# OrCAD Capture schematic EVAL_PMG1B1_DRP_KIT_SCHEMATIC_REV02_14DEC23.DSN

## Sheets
1 11: REVISION HISTORY: title: EVAL_PMG1_B1_DRP Kit; rev: 02; note: 630-60657-01
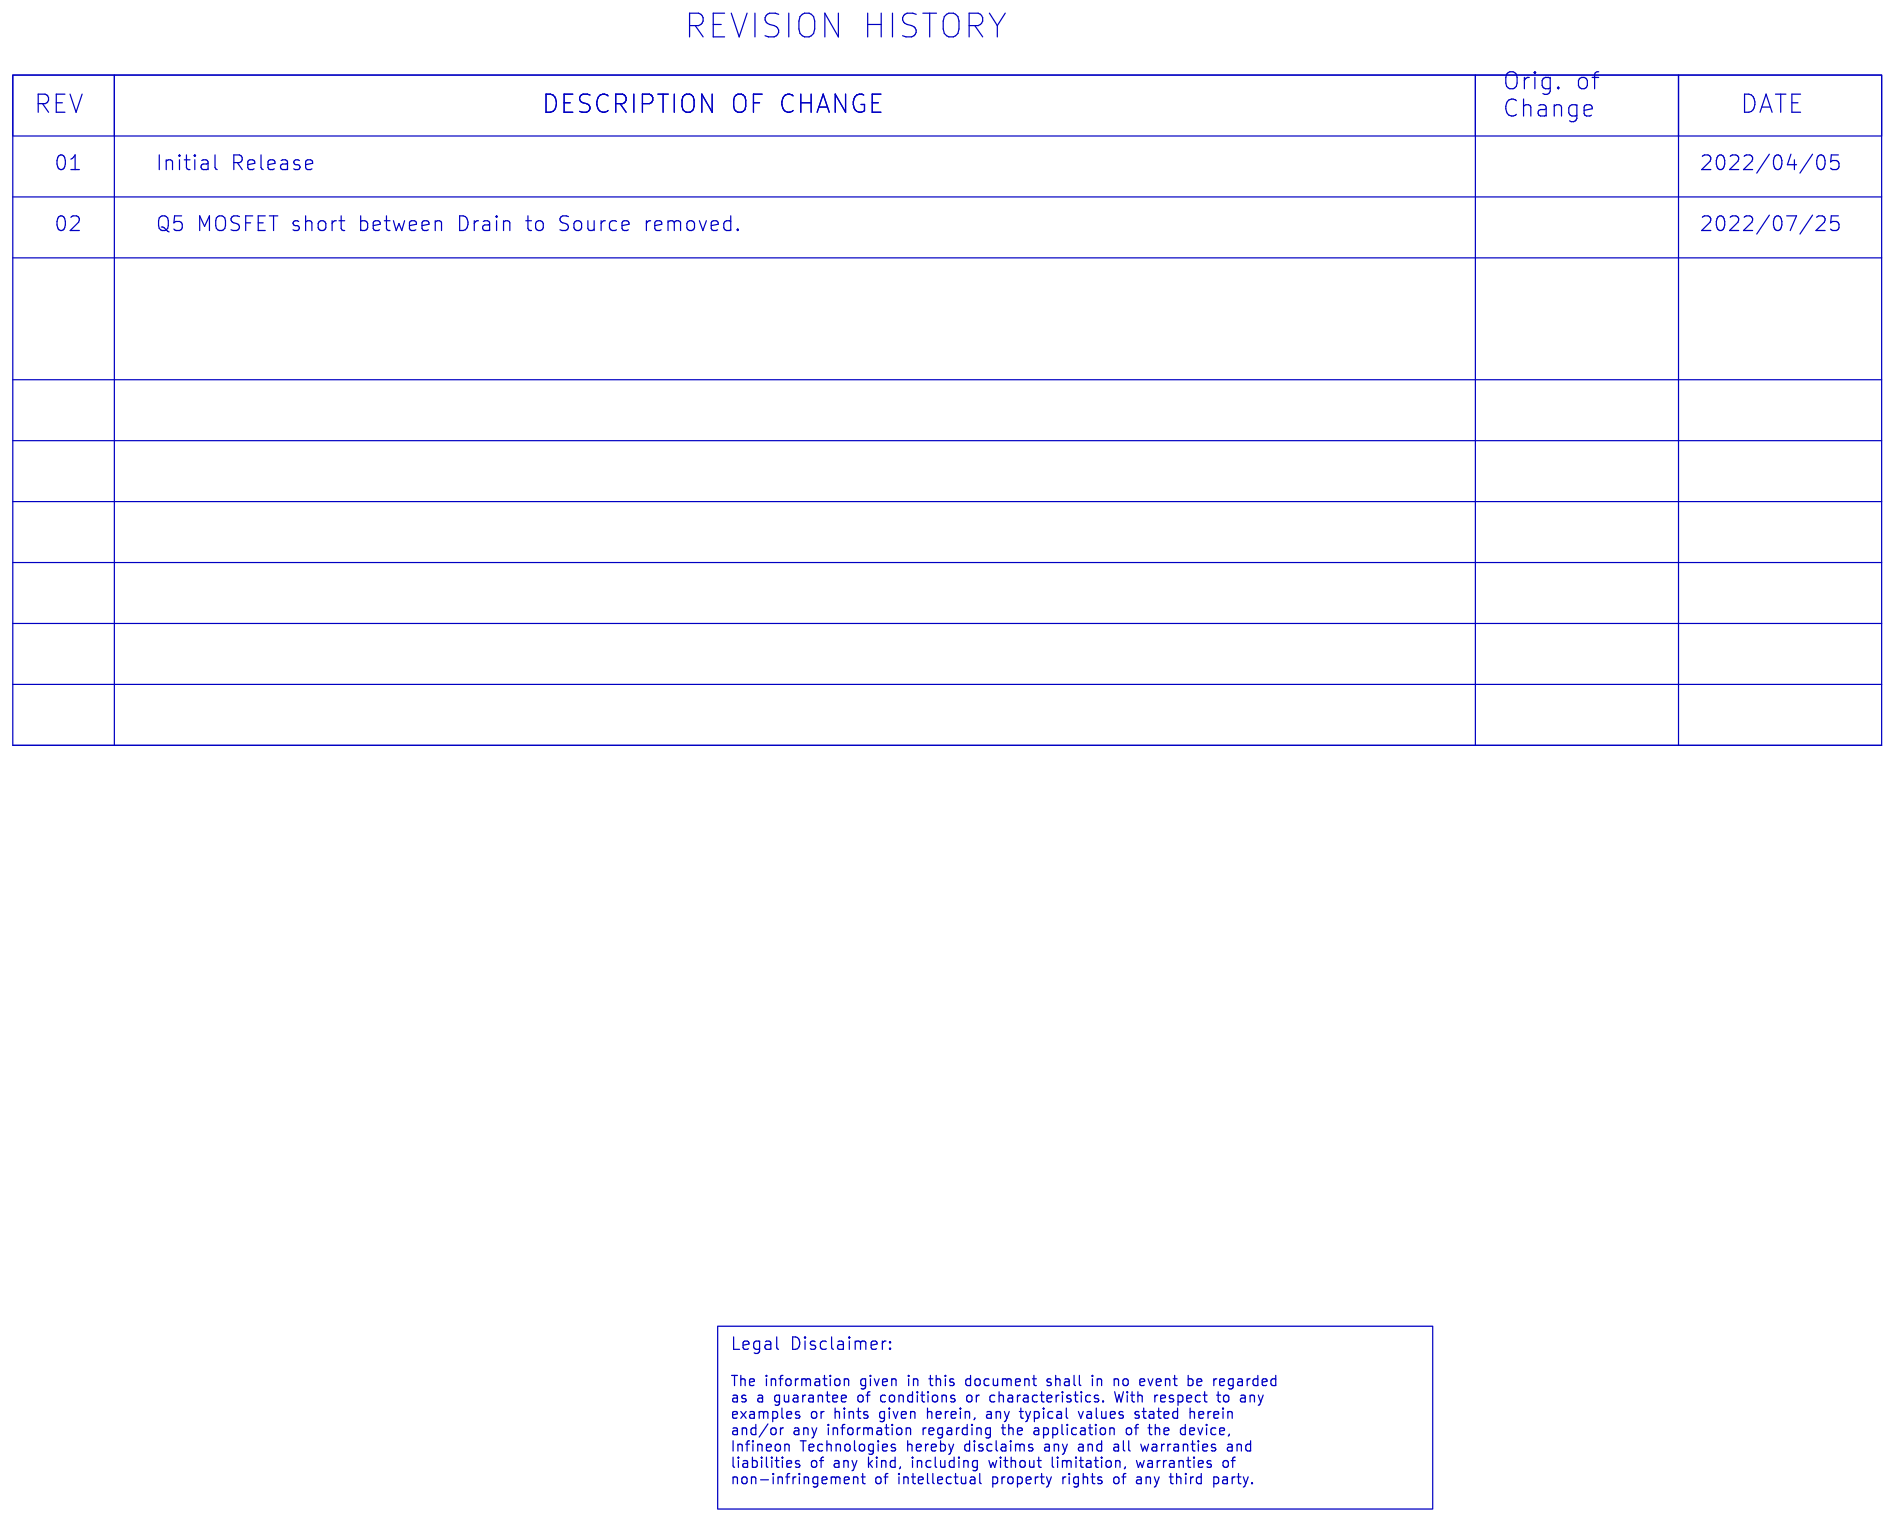
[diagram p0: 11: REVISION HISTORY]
2 10: ACCESSORIES
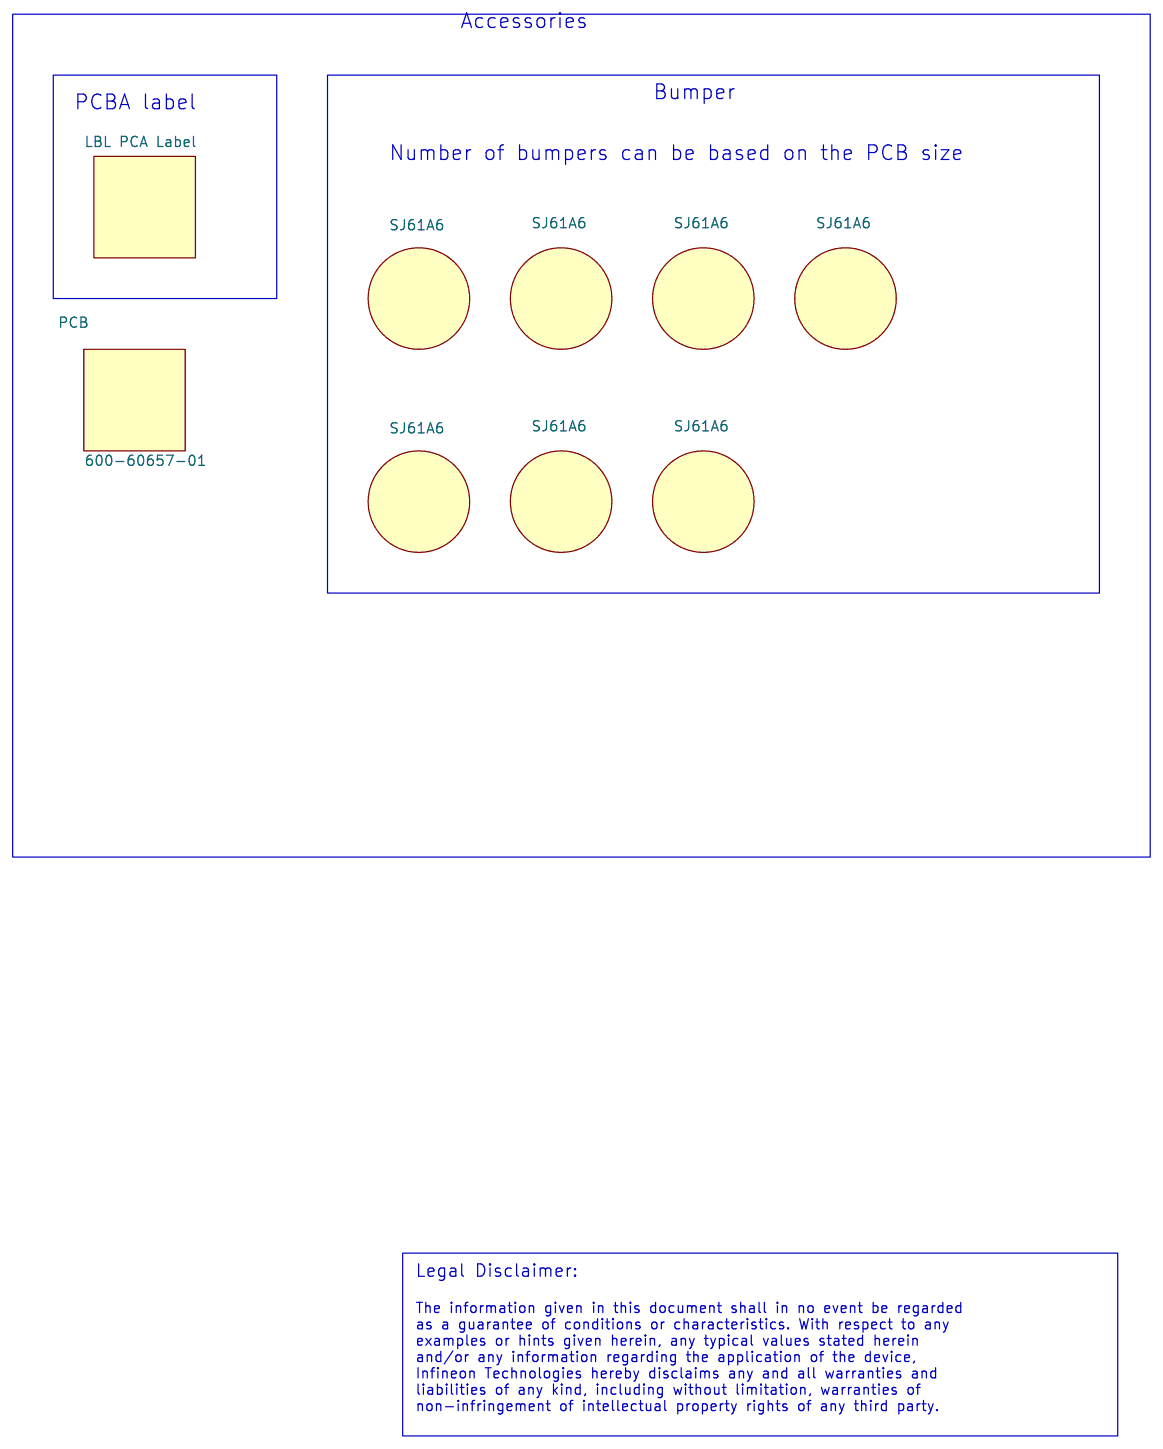
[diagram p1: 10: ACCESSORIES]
3 03: KITPROG3: size A4
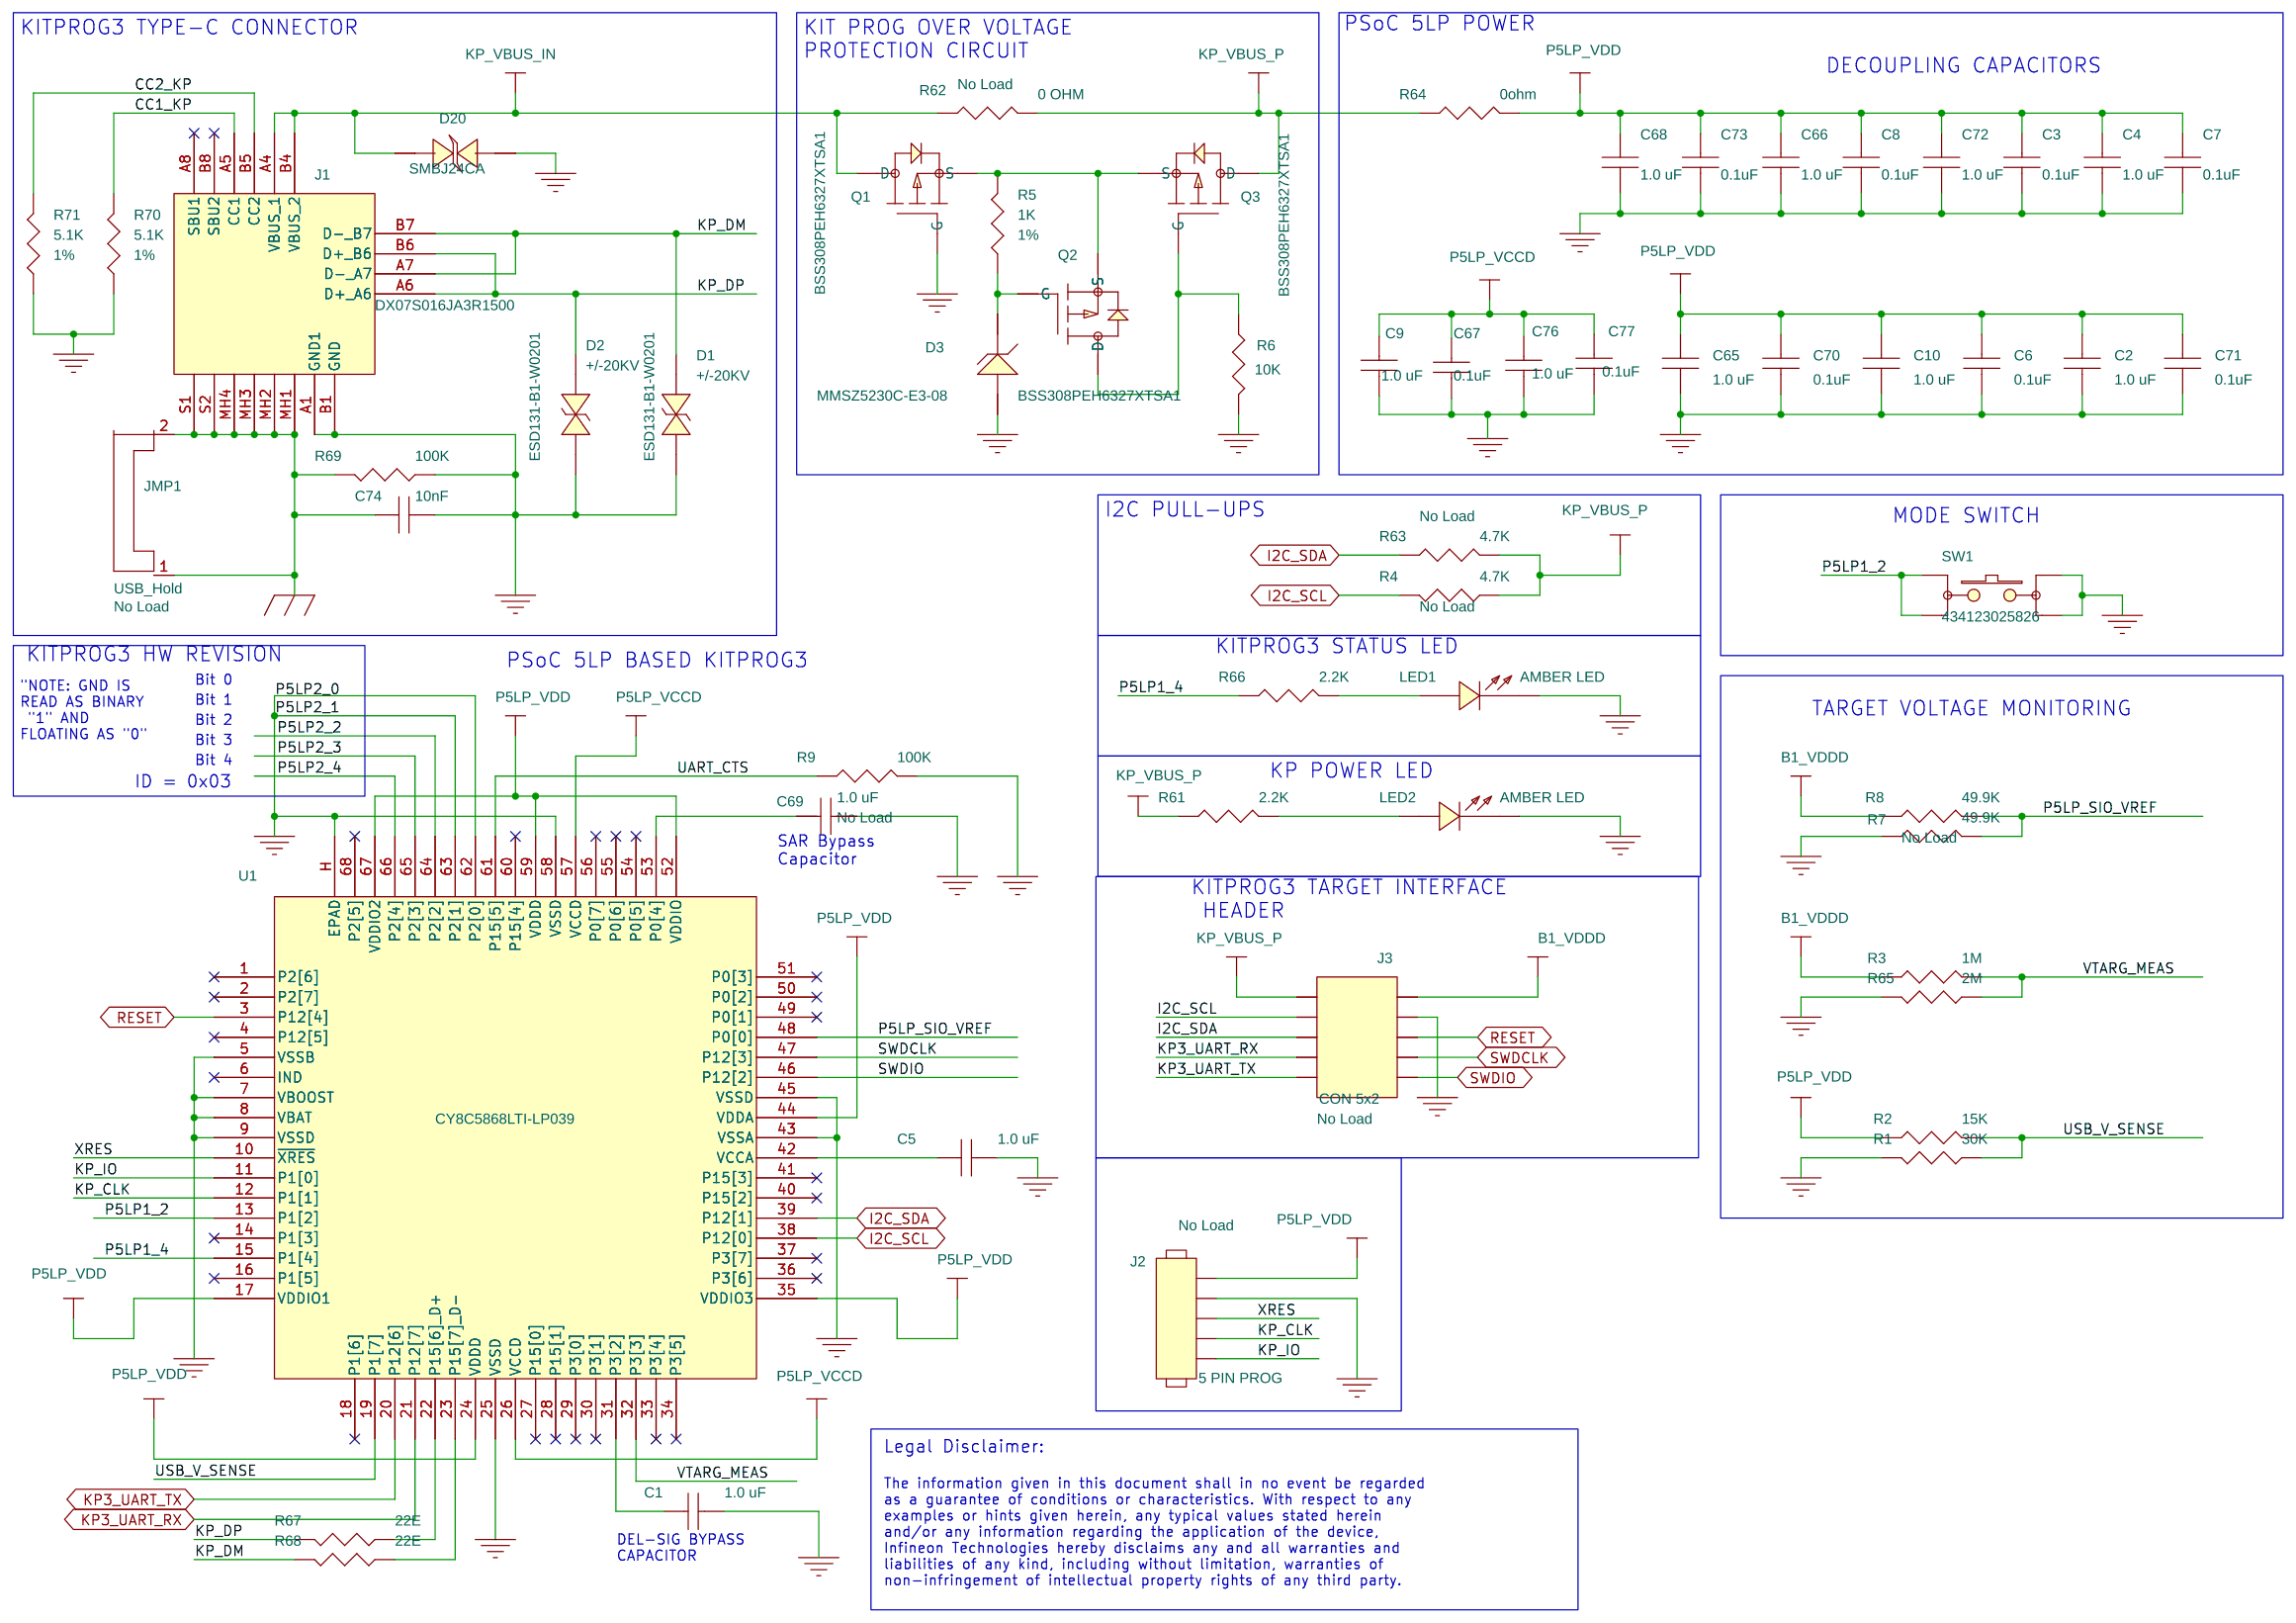
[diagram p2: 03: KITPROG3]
4 02: BLOCK DIAGRAM
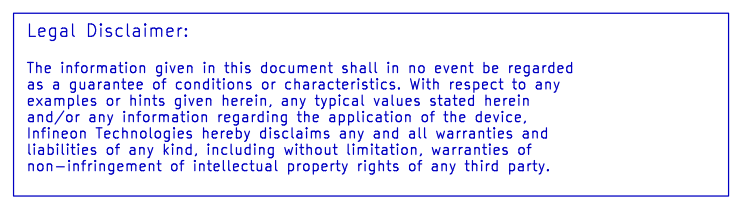
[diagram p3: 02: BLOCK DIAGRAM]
5 05: PMG1-B1 CONTROLLER: size A4
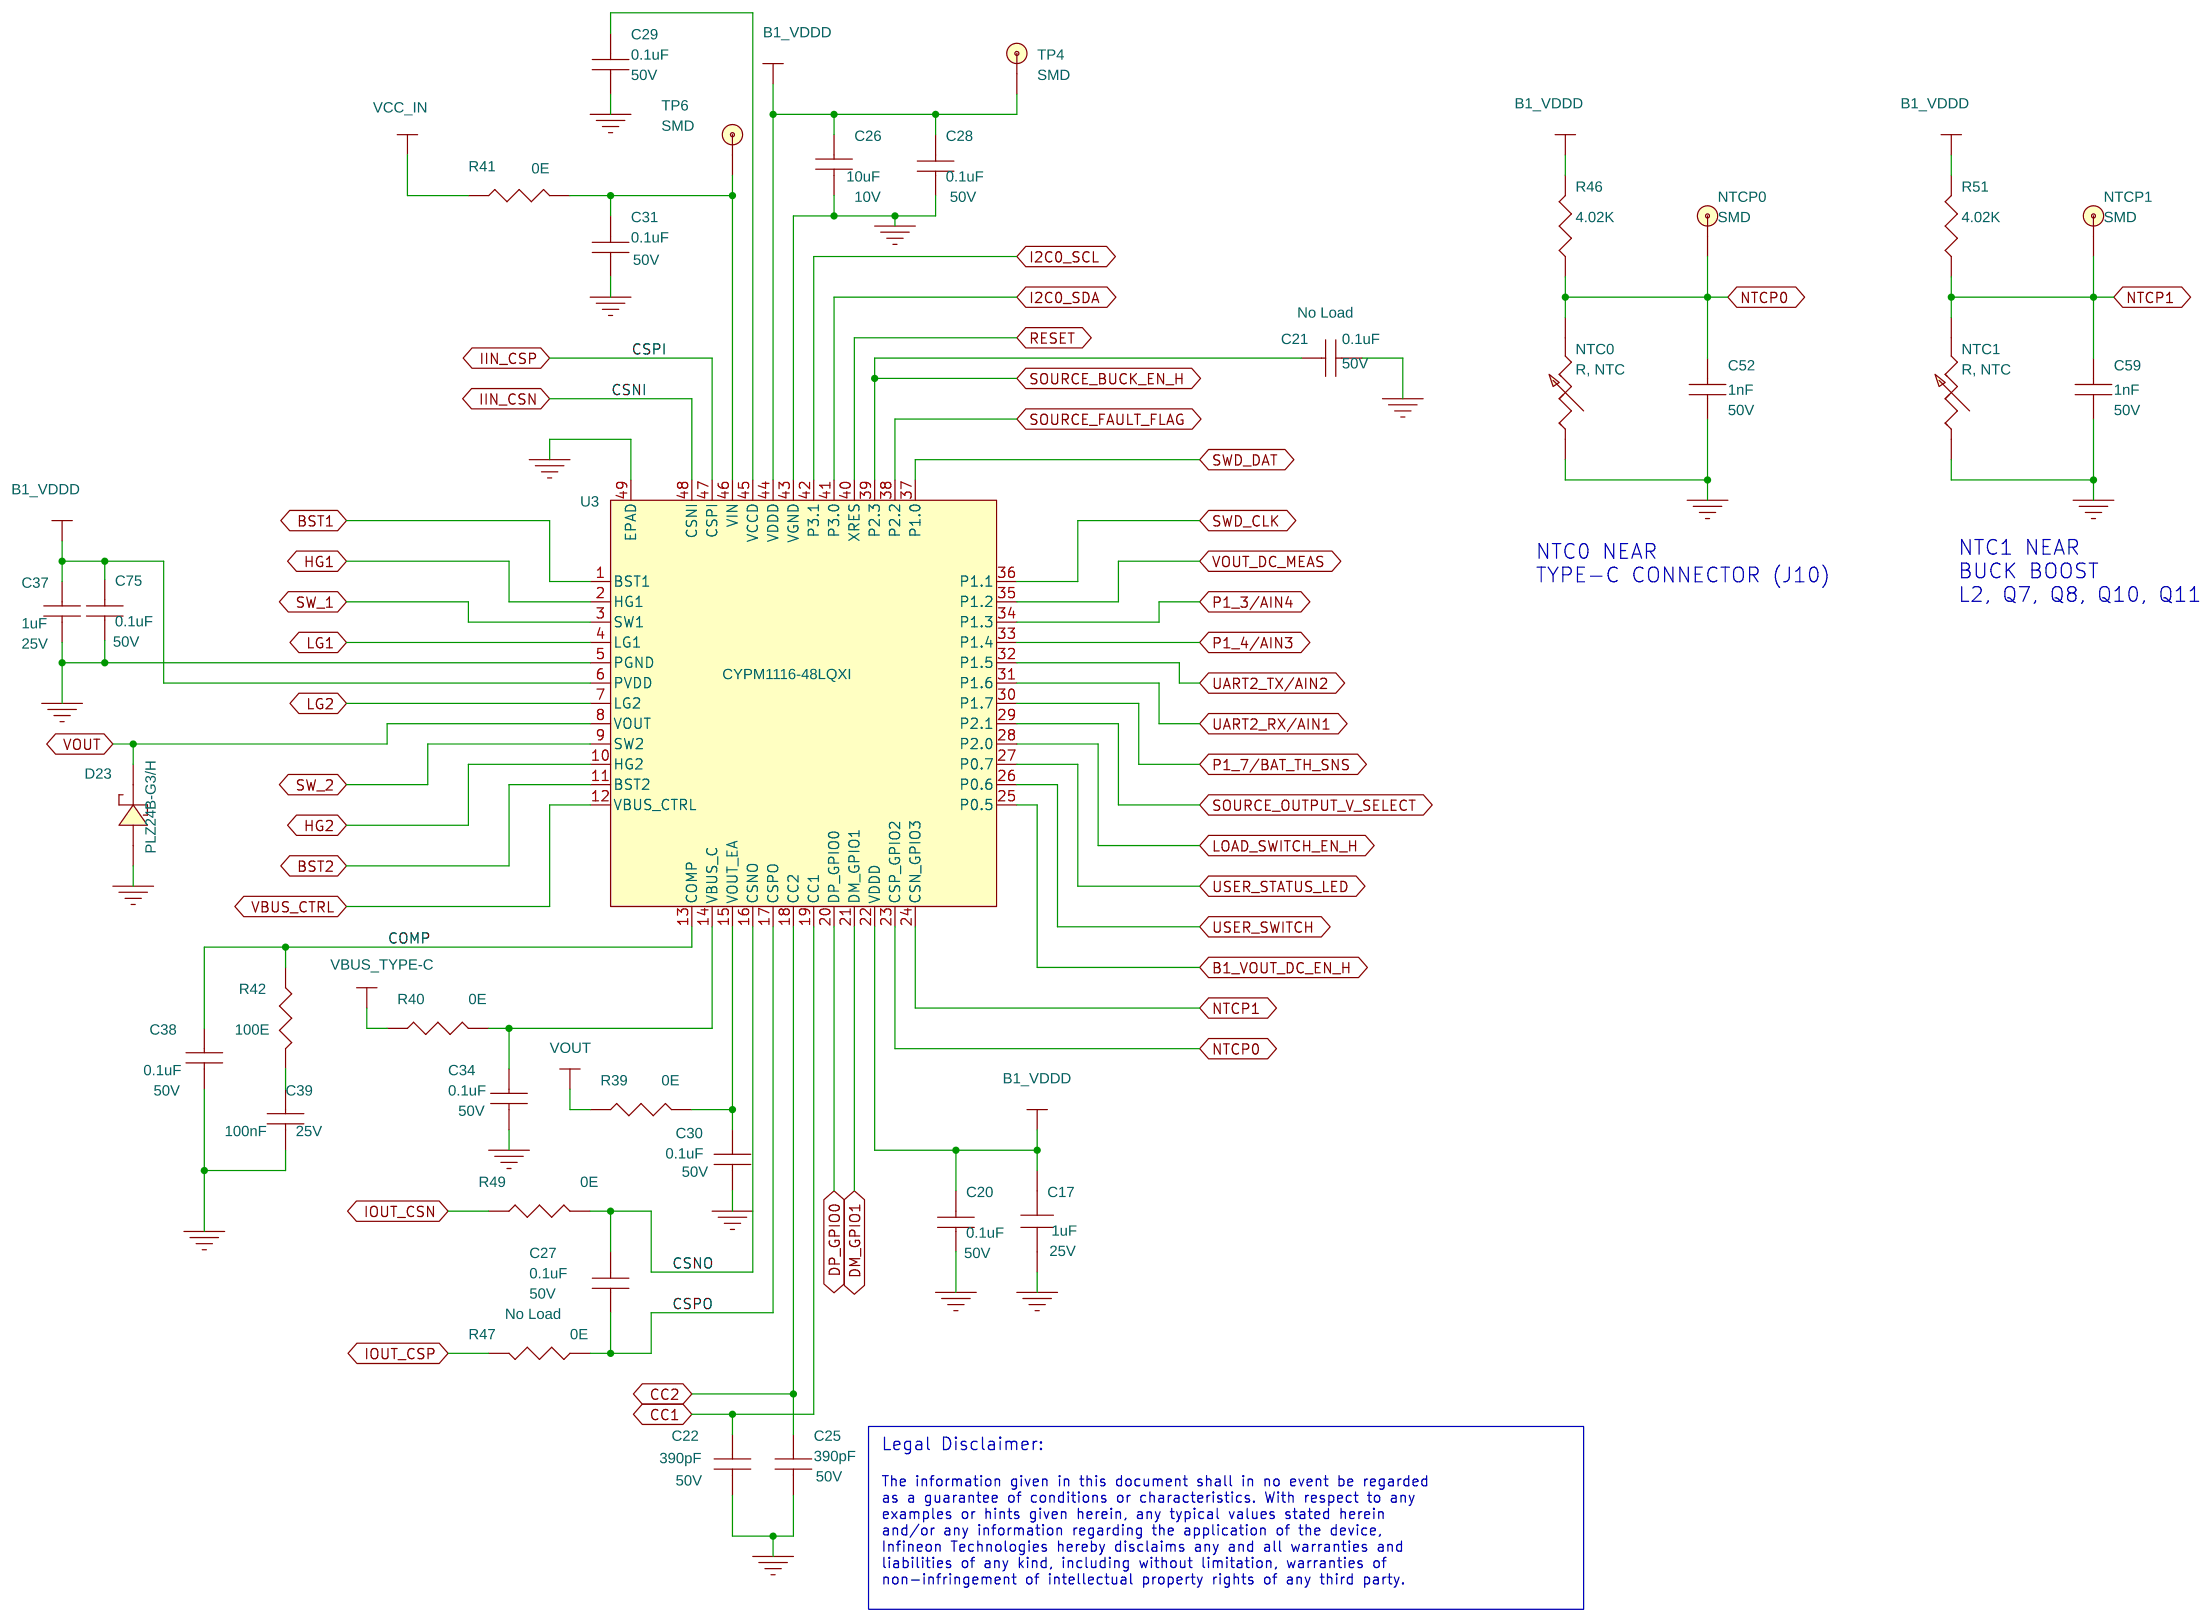
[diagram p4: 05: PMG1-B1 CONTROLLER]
6 06: INTERFACE SIGNALS: size A4
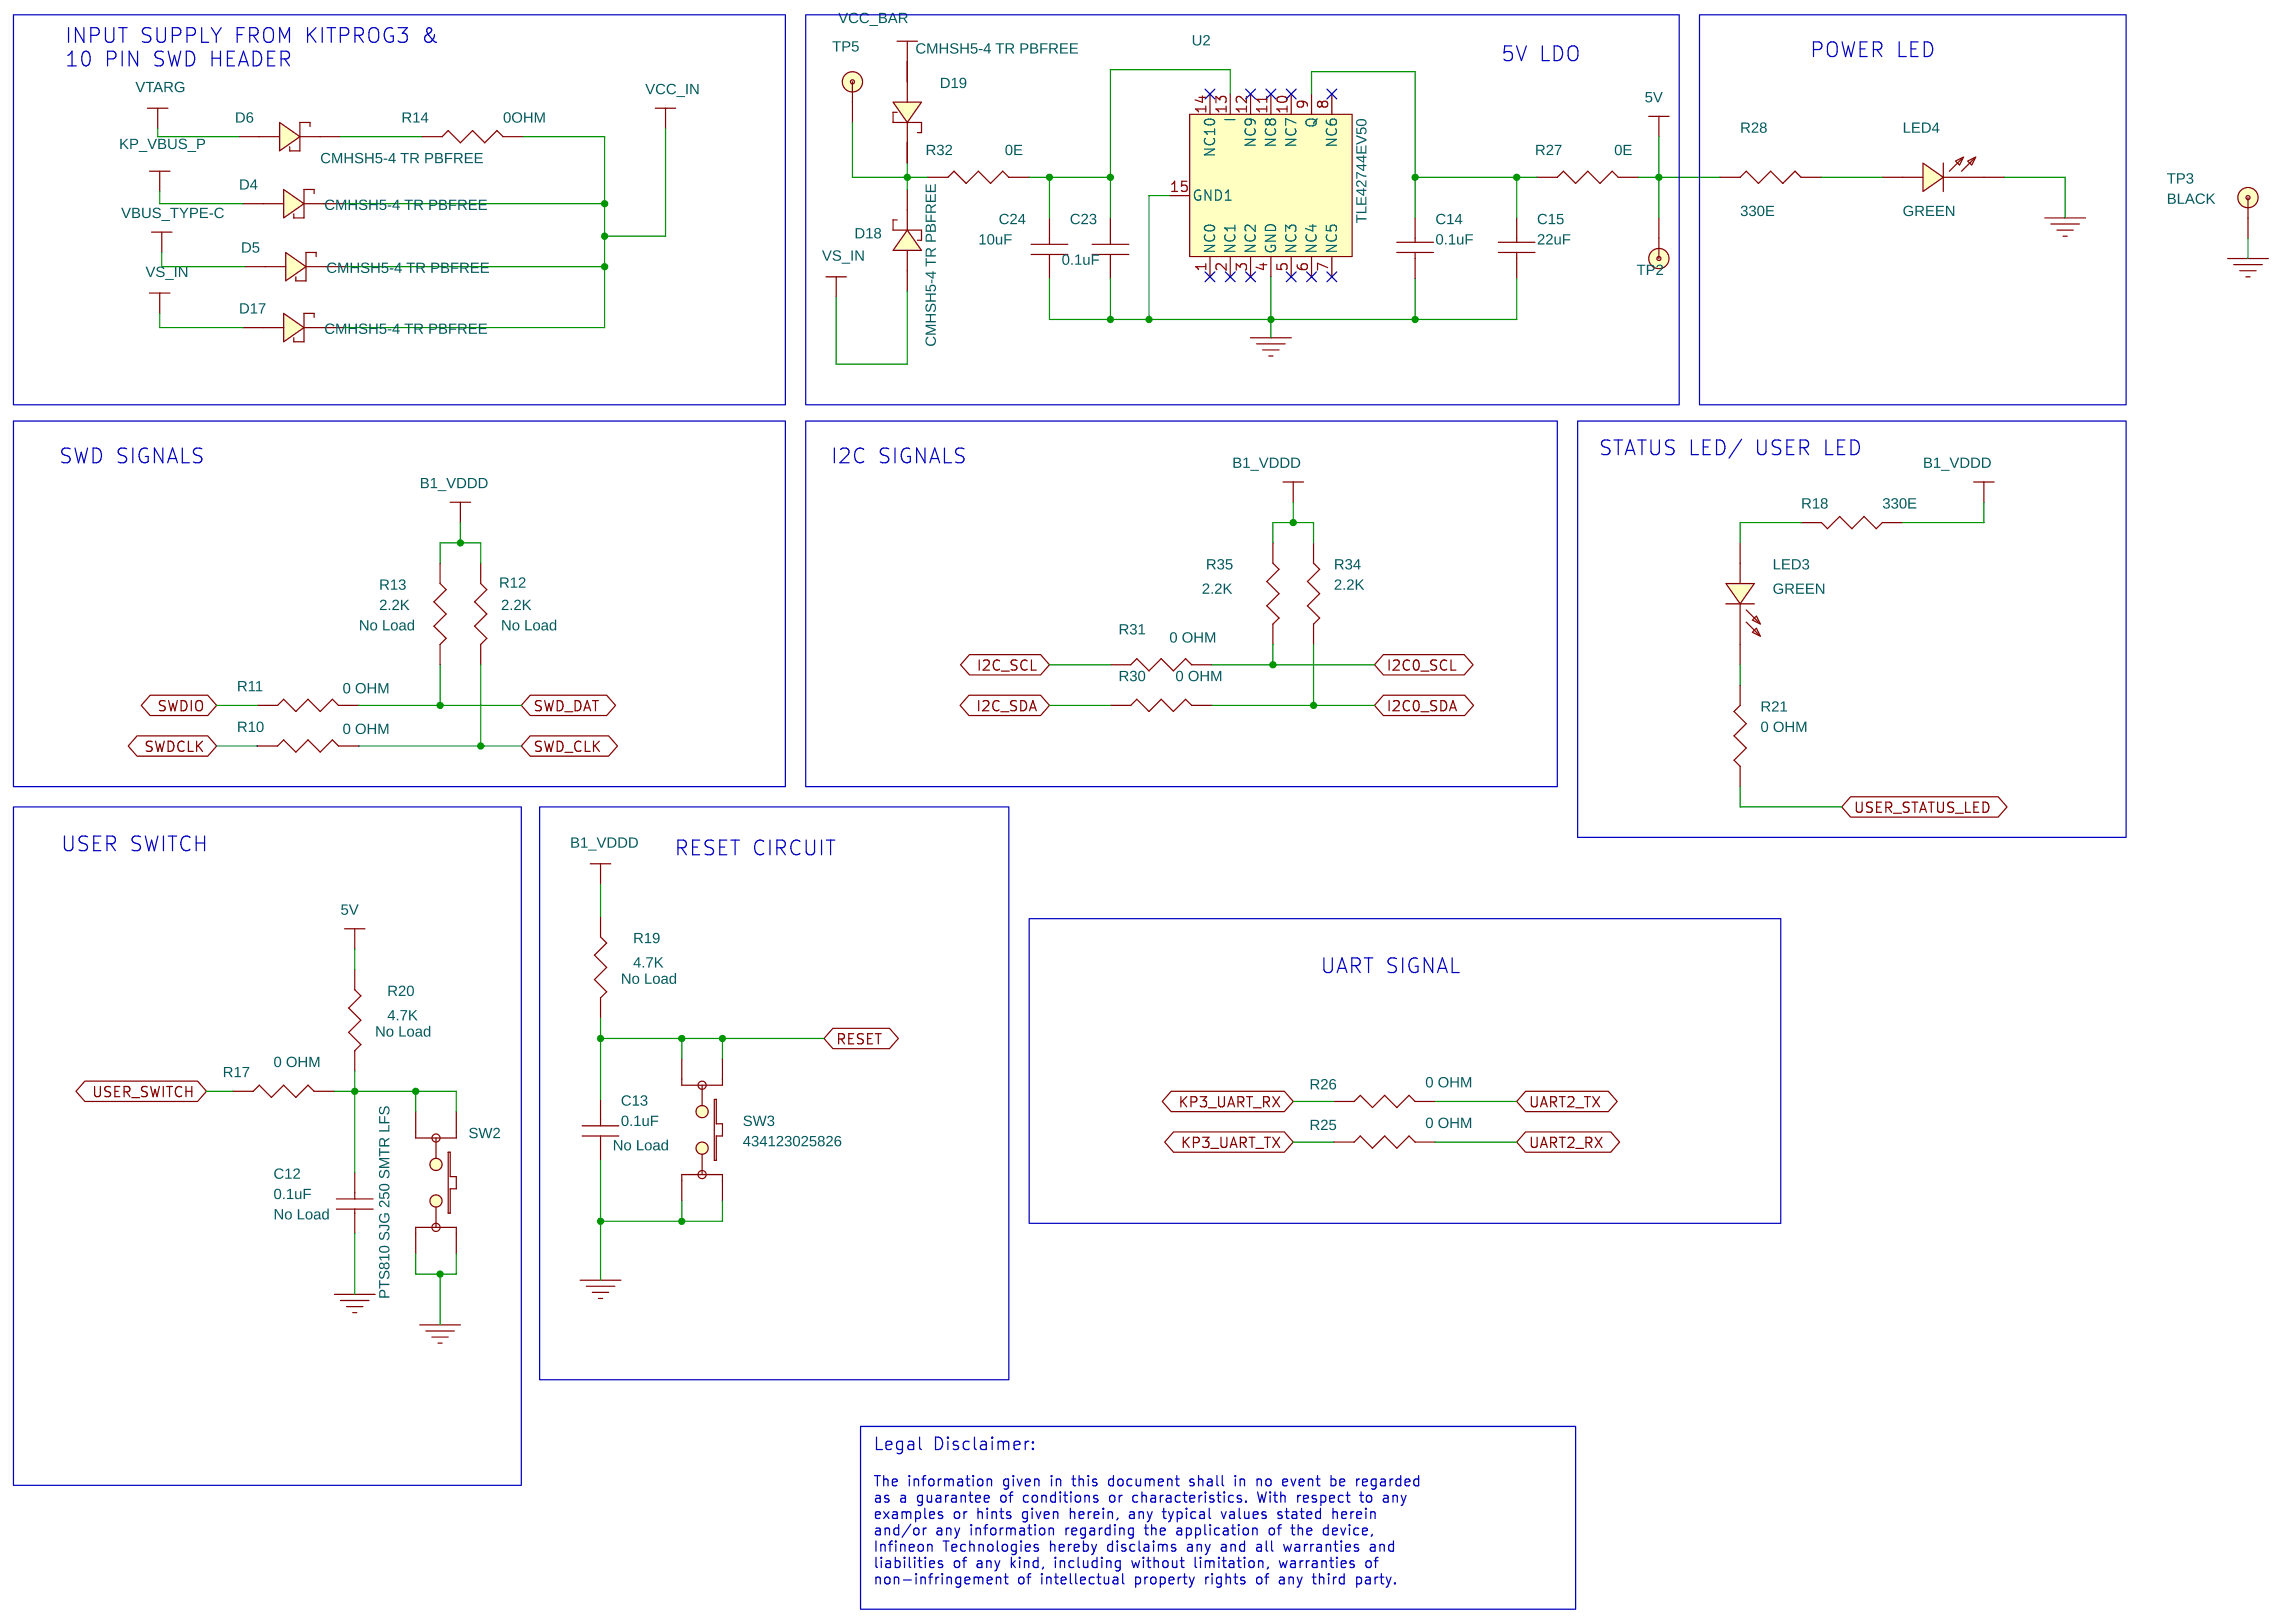
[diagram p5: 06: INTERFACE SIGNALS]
7 08: SOURCE BUCK (27W MAX): size A4
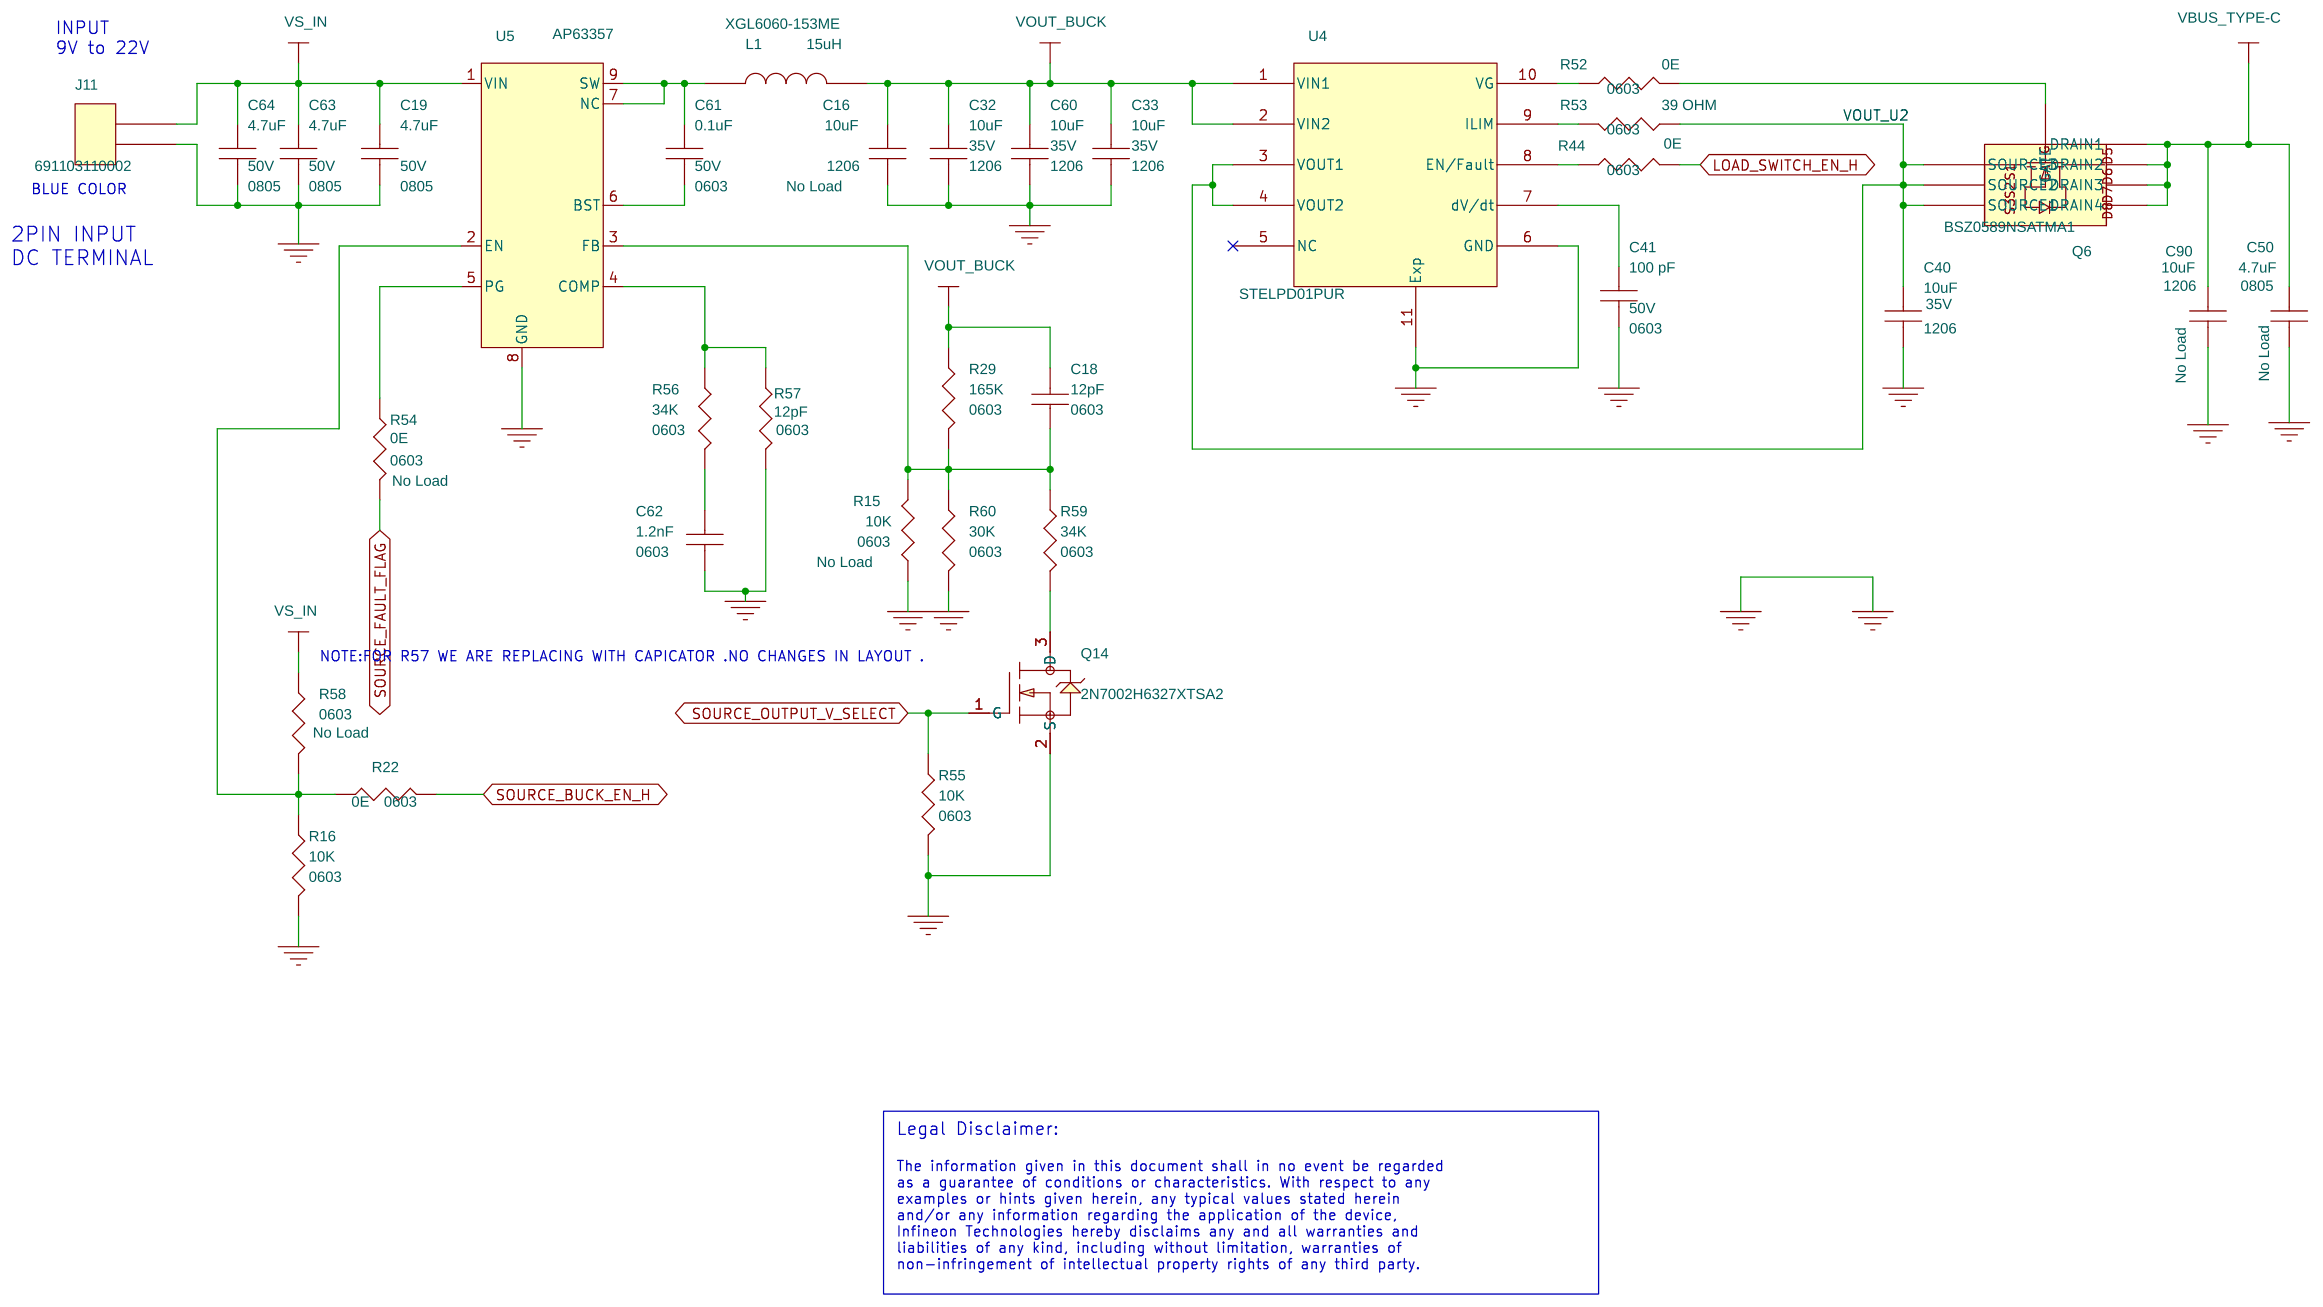
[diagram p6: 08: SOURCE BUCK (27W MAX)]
8 07: CONNECTOR INTERFACES: size A4
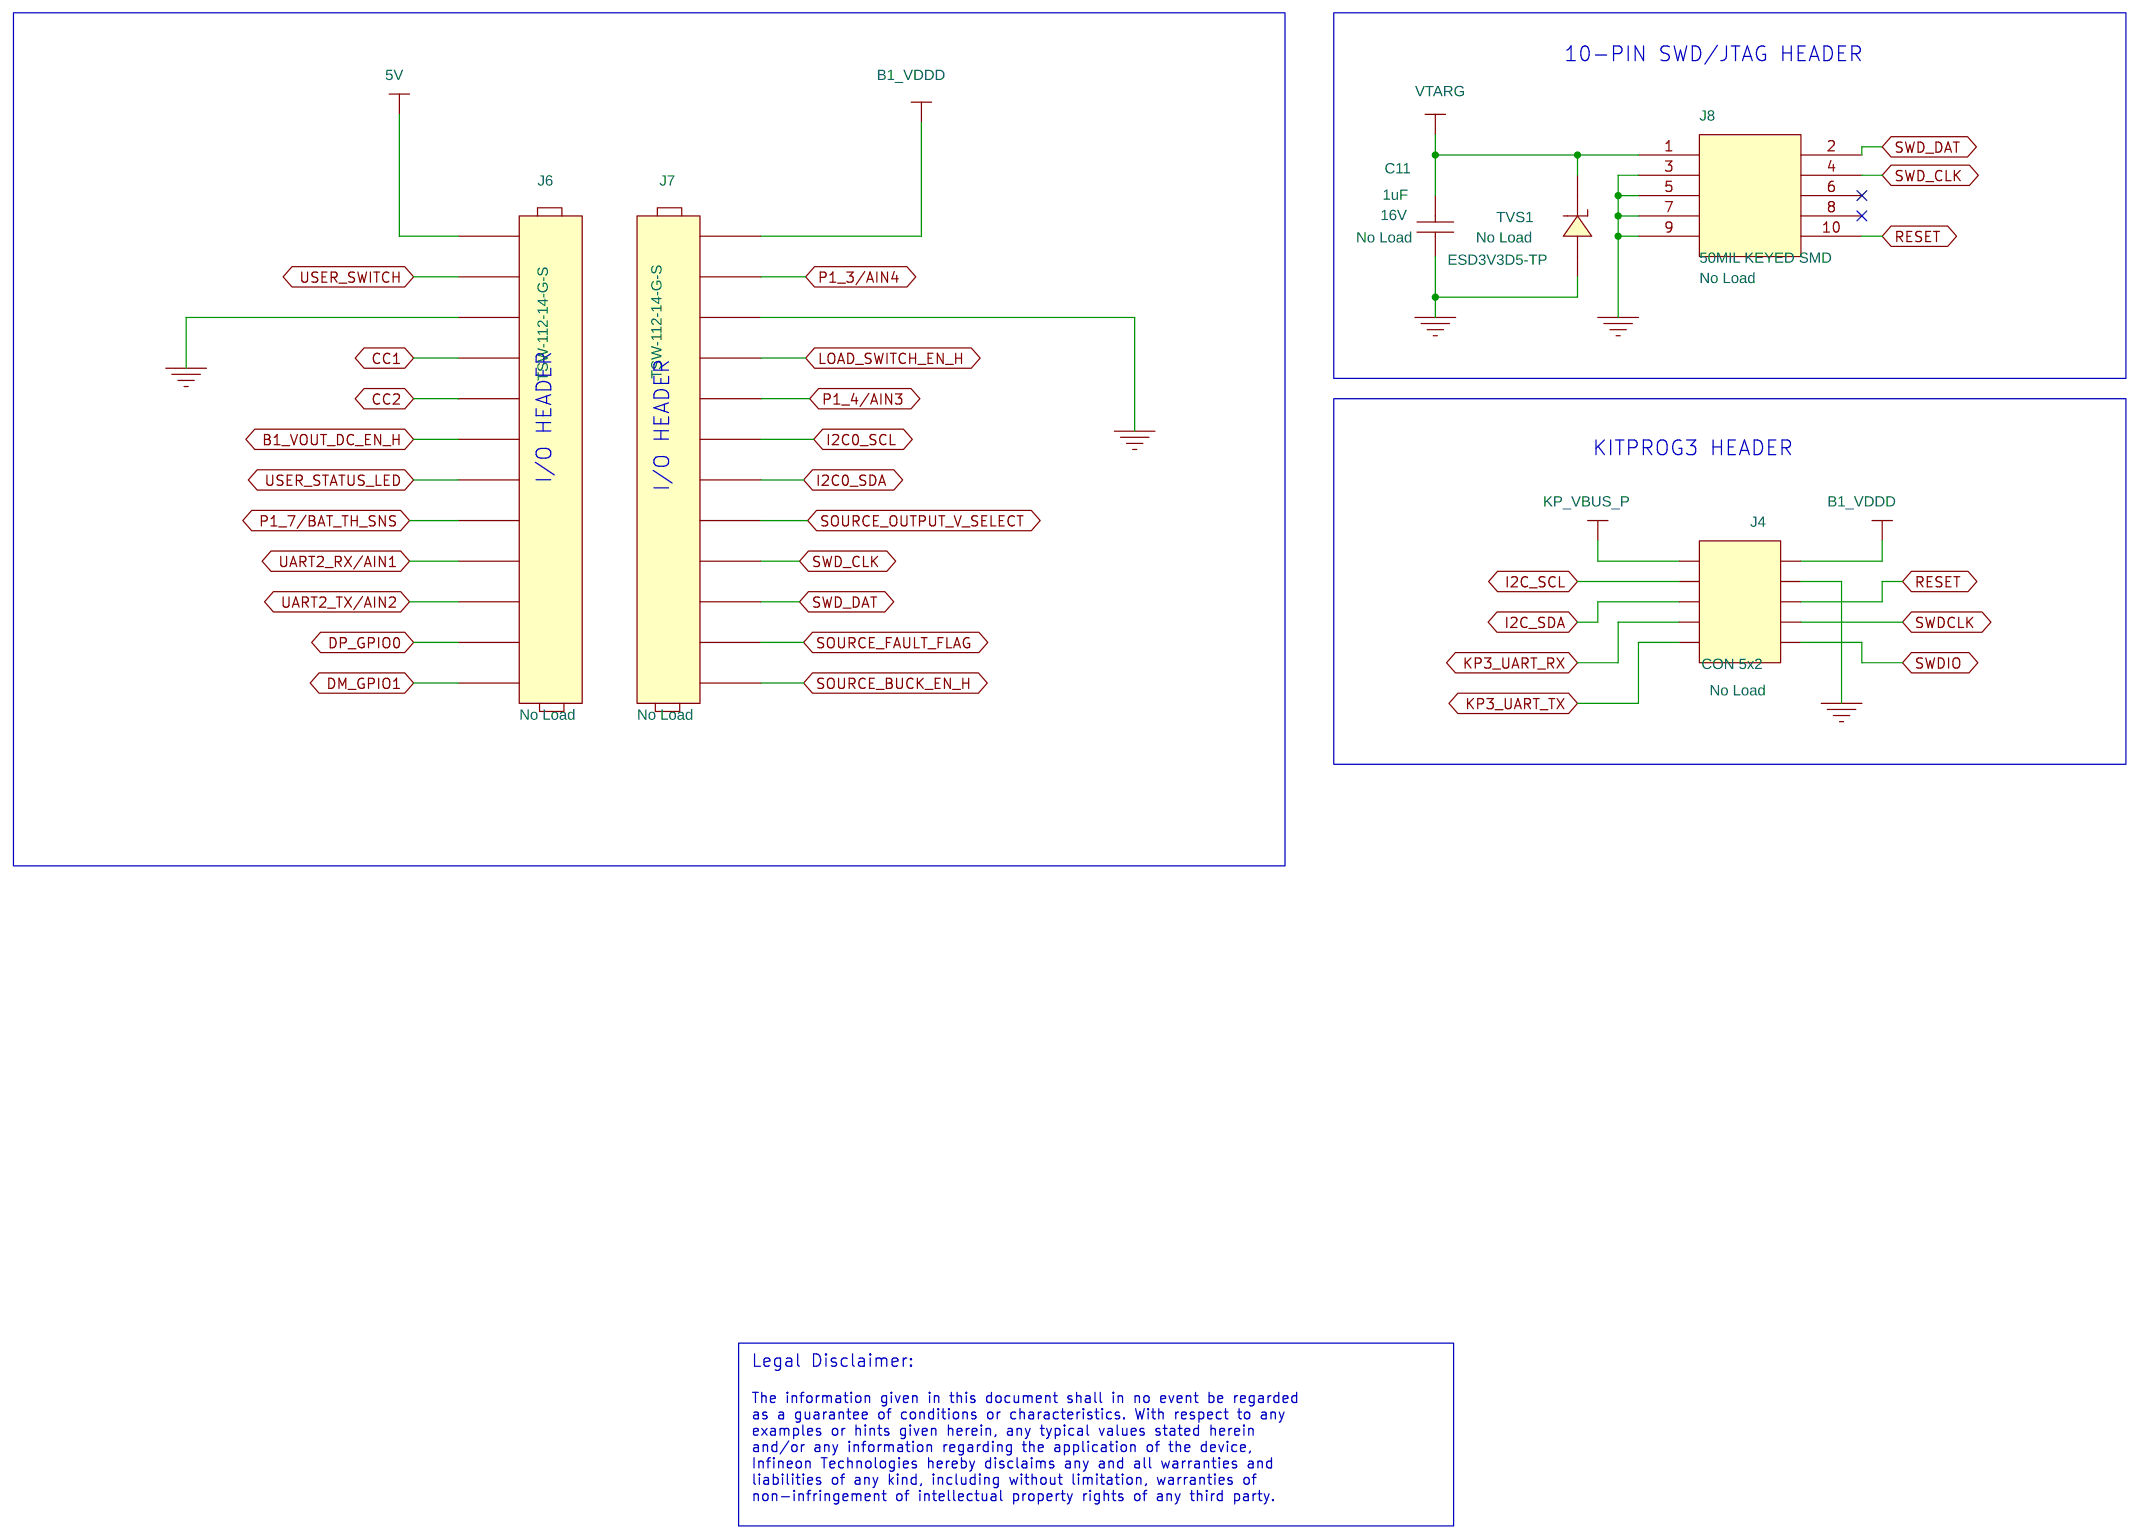
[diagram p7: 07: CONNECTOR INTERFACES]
9 09: BATTERY CELL & TEMPERATURE: size A4
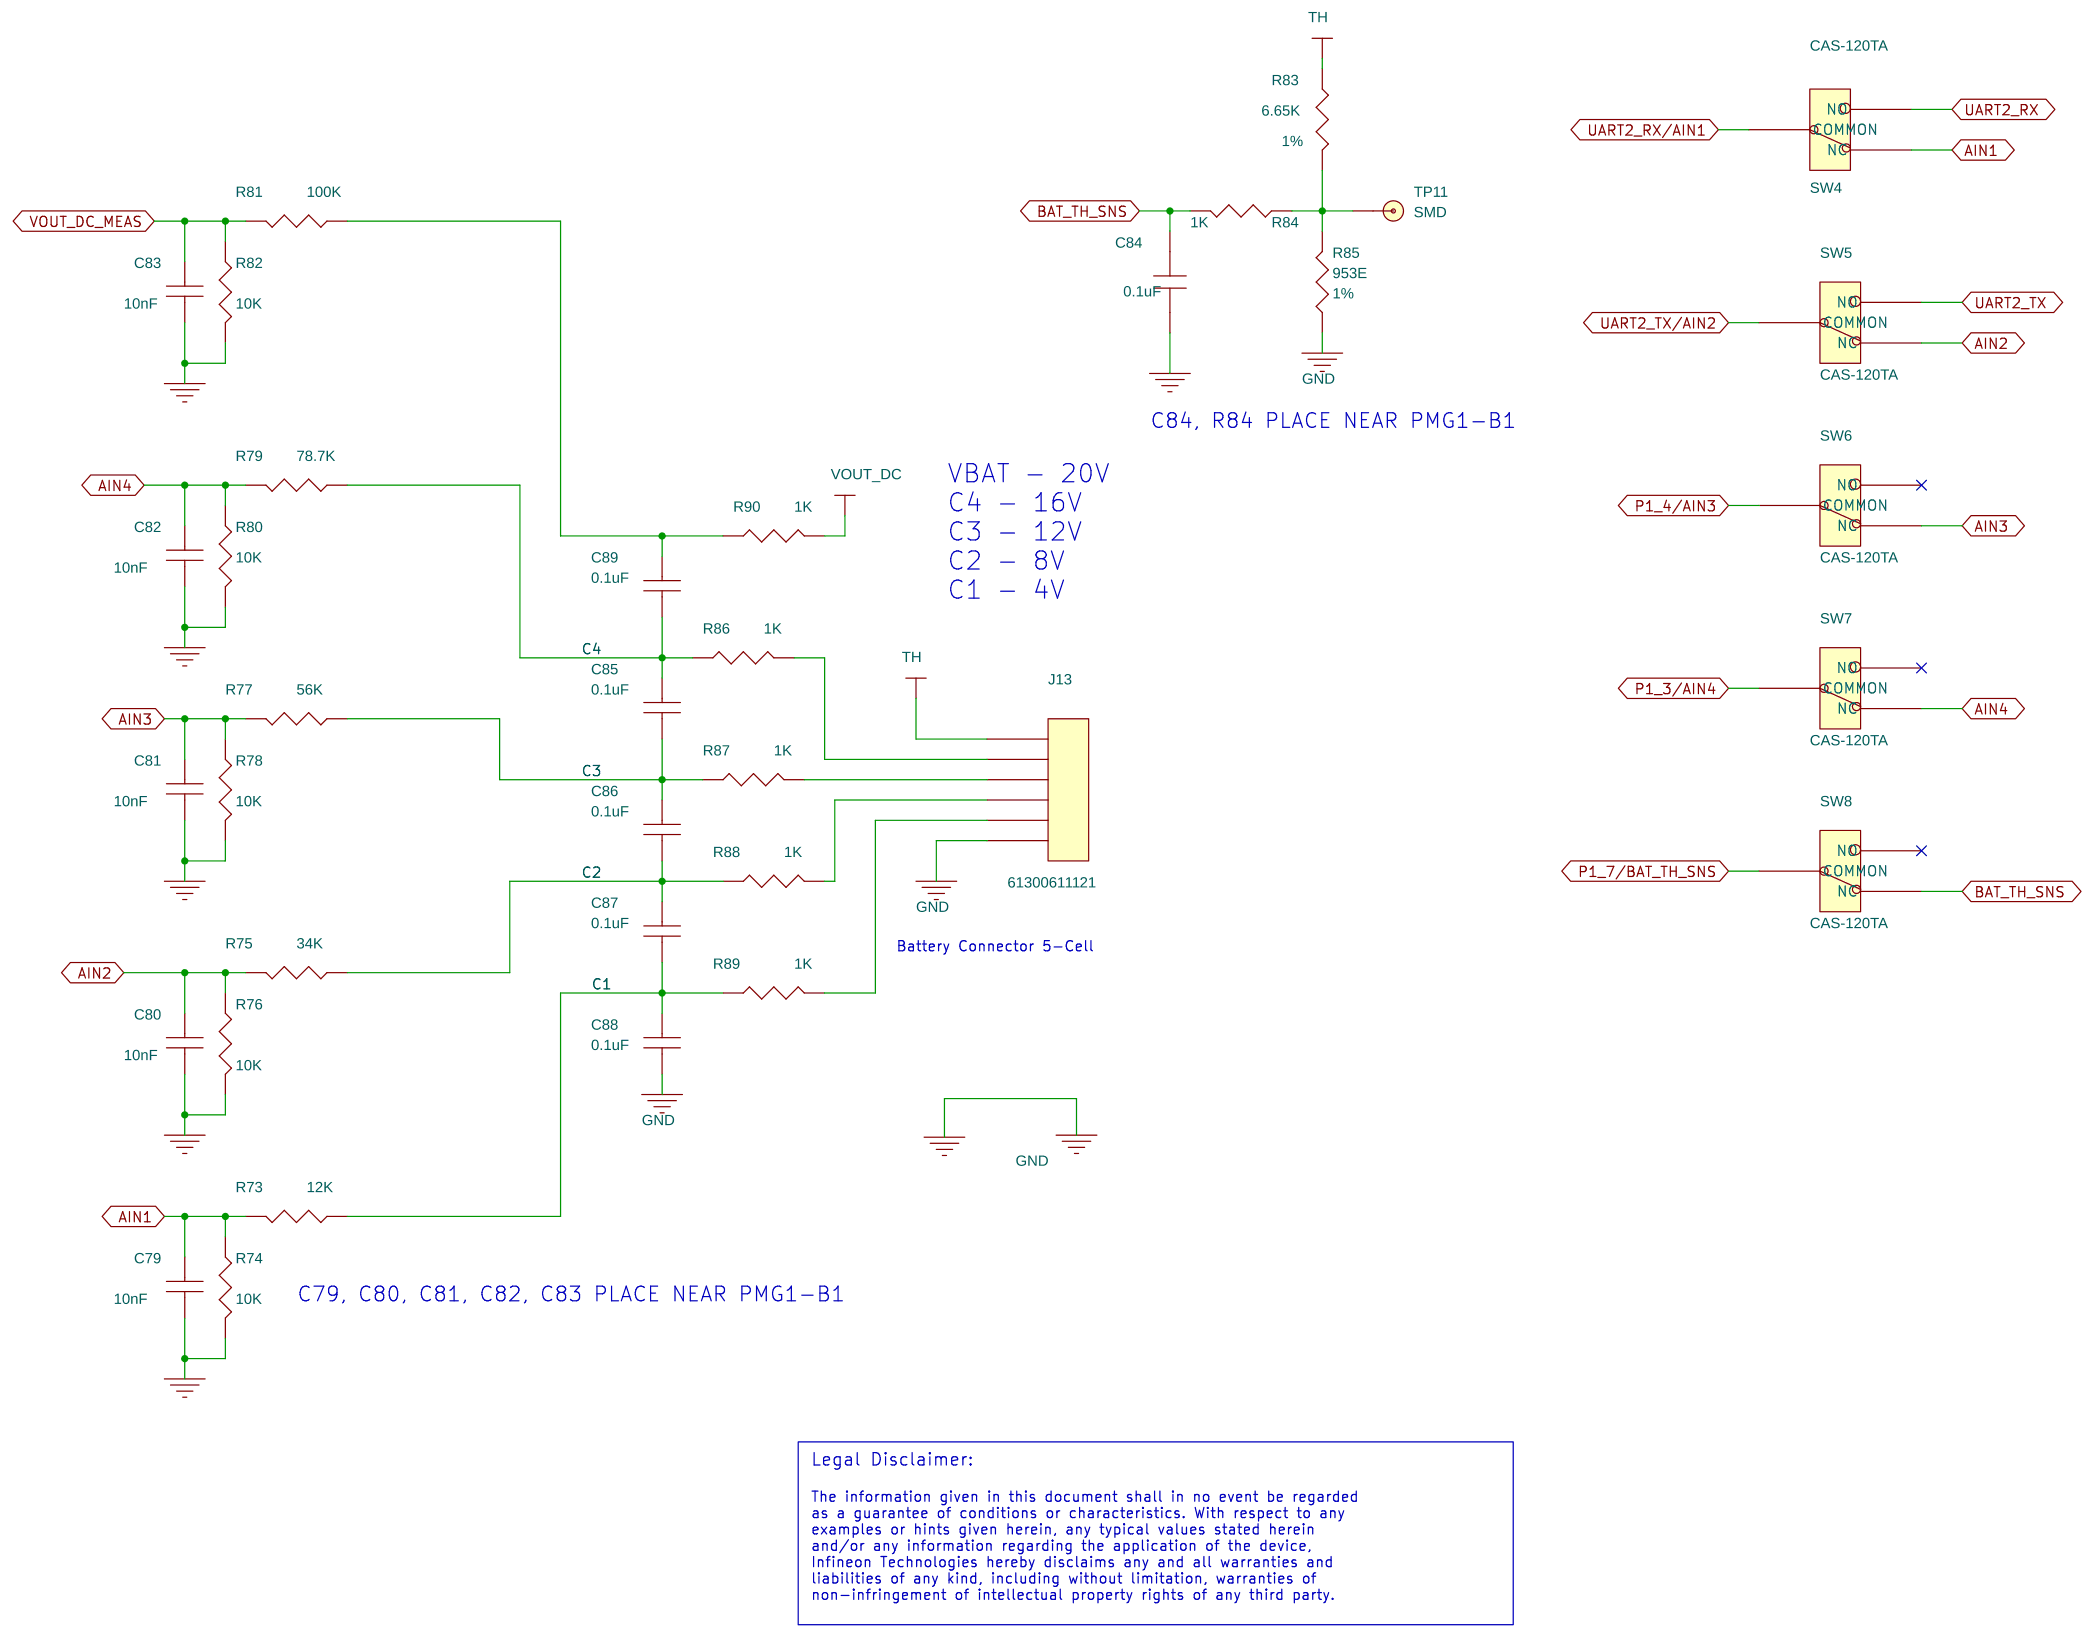
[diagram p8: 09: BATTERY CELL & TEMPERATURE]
10 01: TITLE & TABLE OF CONTENTS
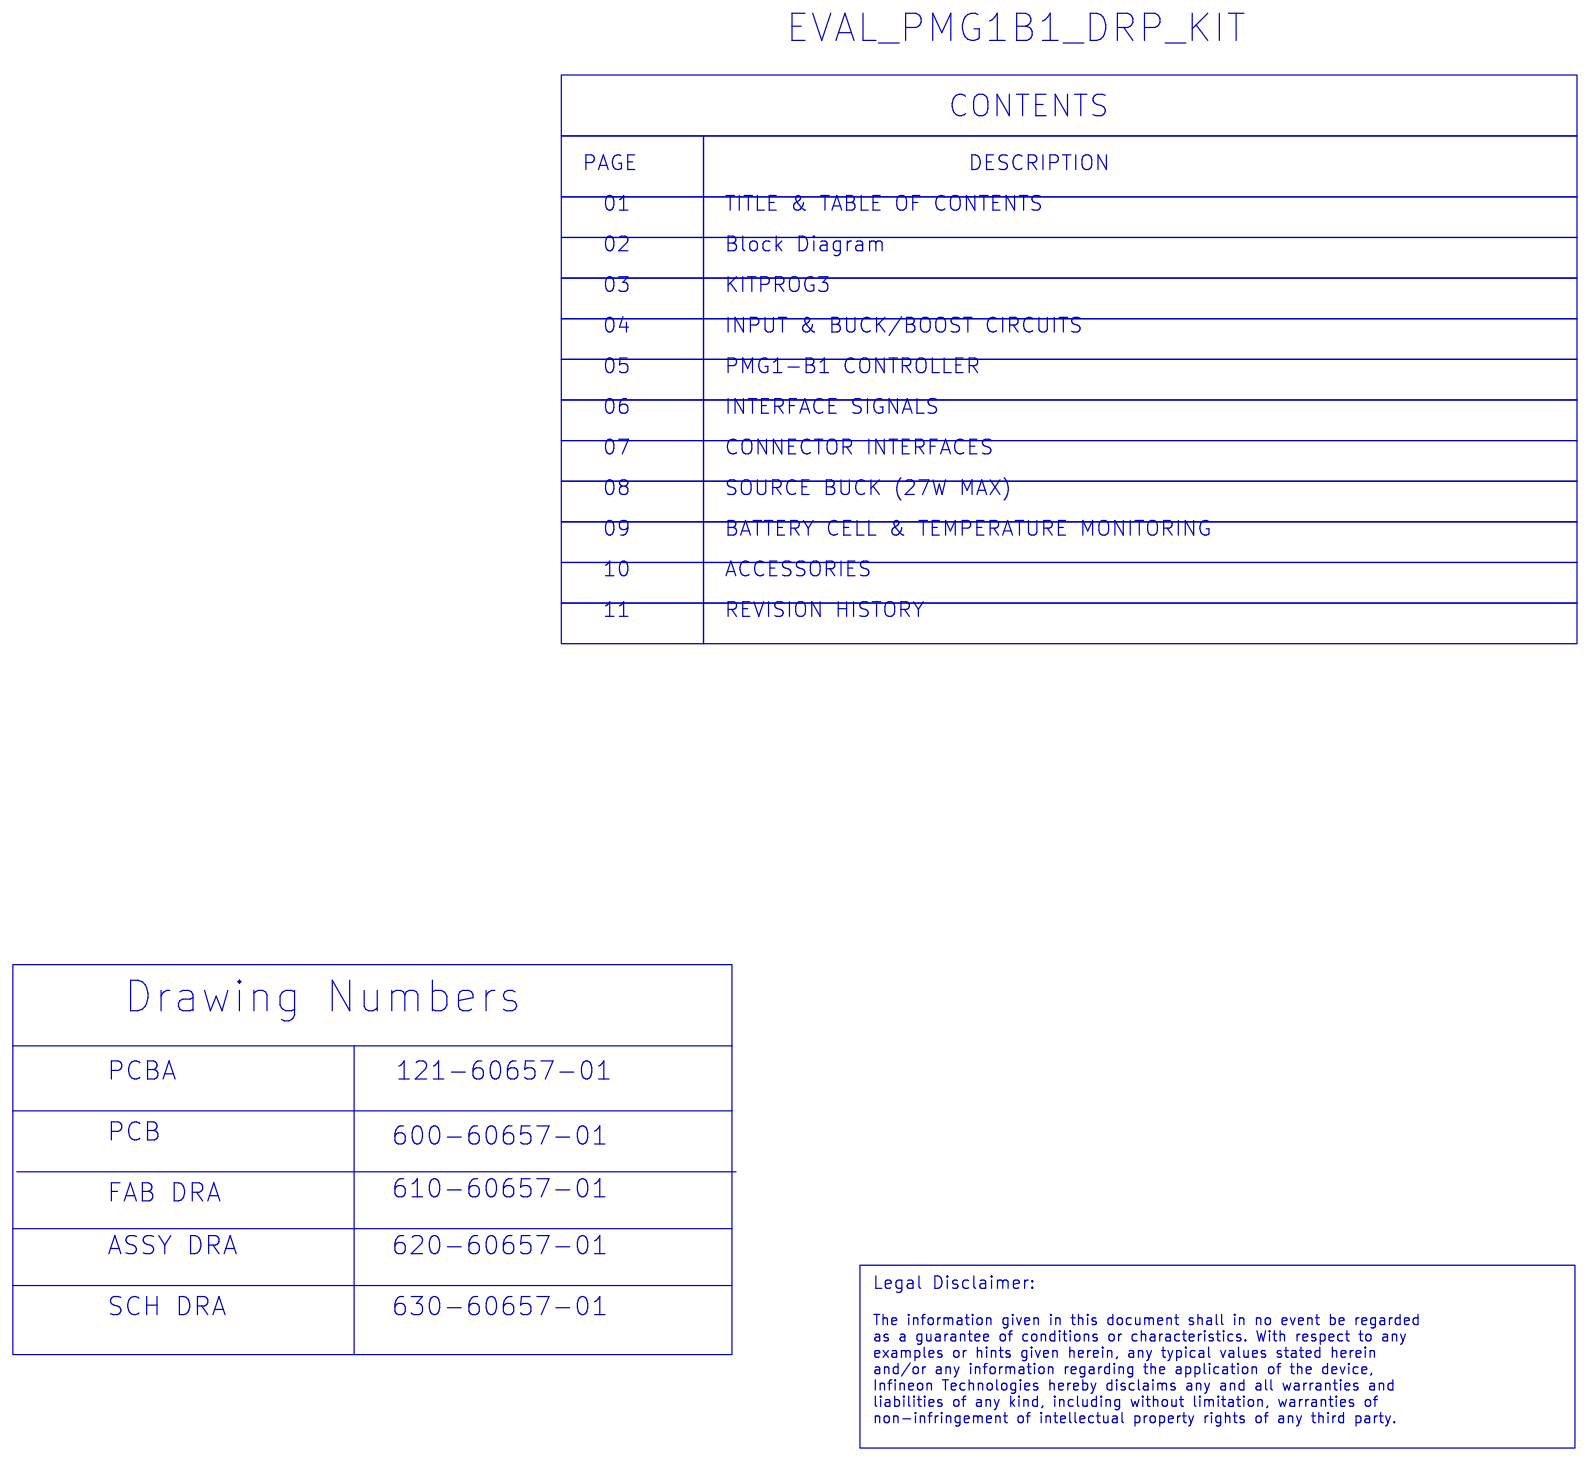
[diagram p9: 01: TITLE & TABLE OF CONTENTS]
11 04: INPUT & BUCK/BOOST CIRCUITS: size A3
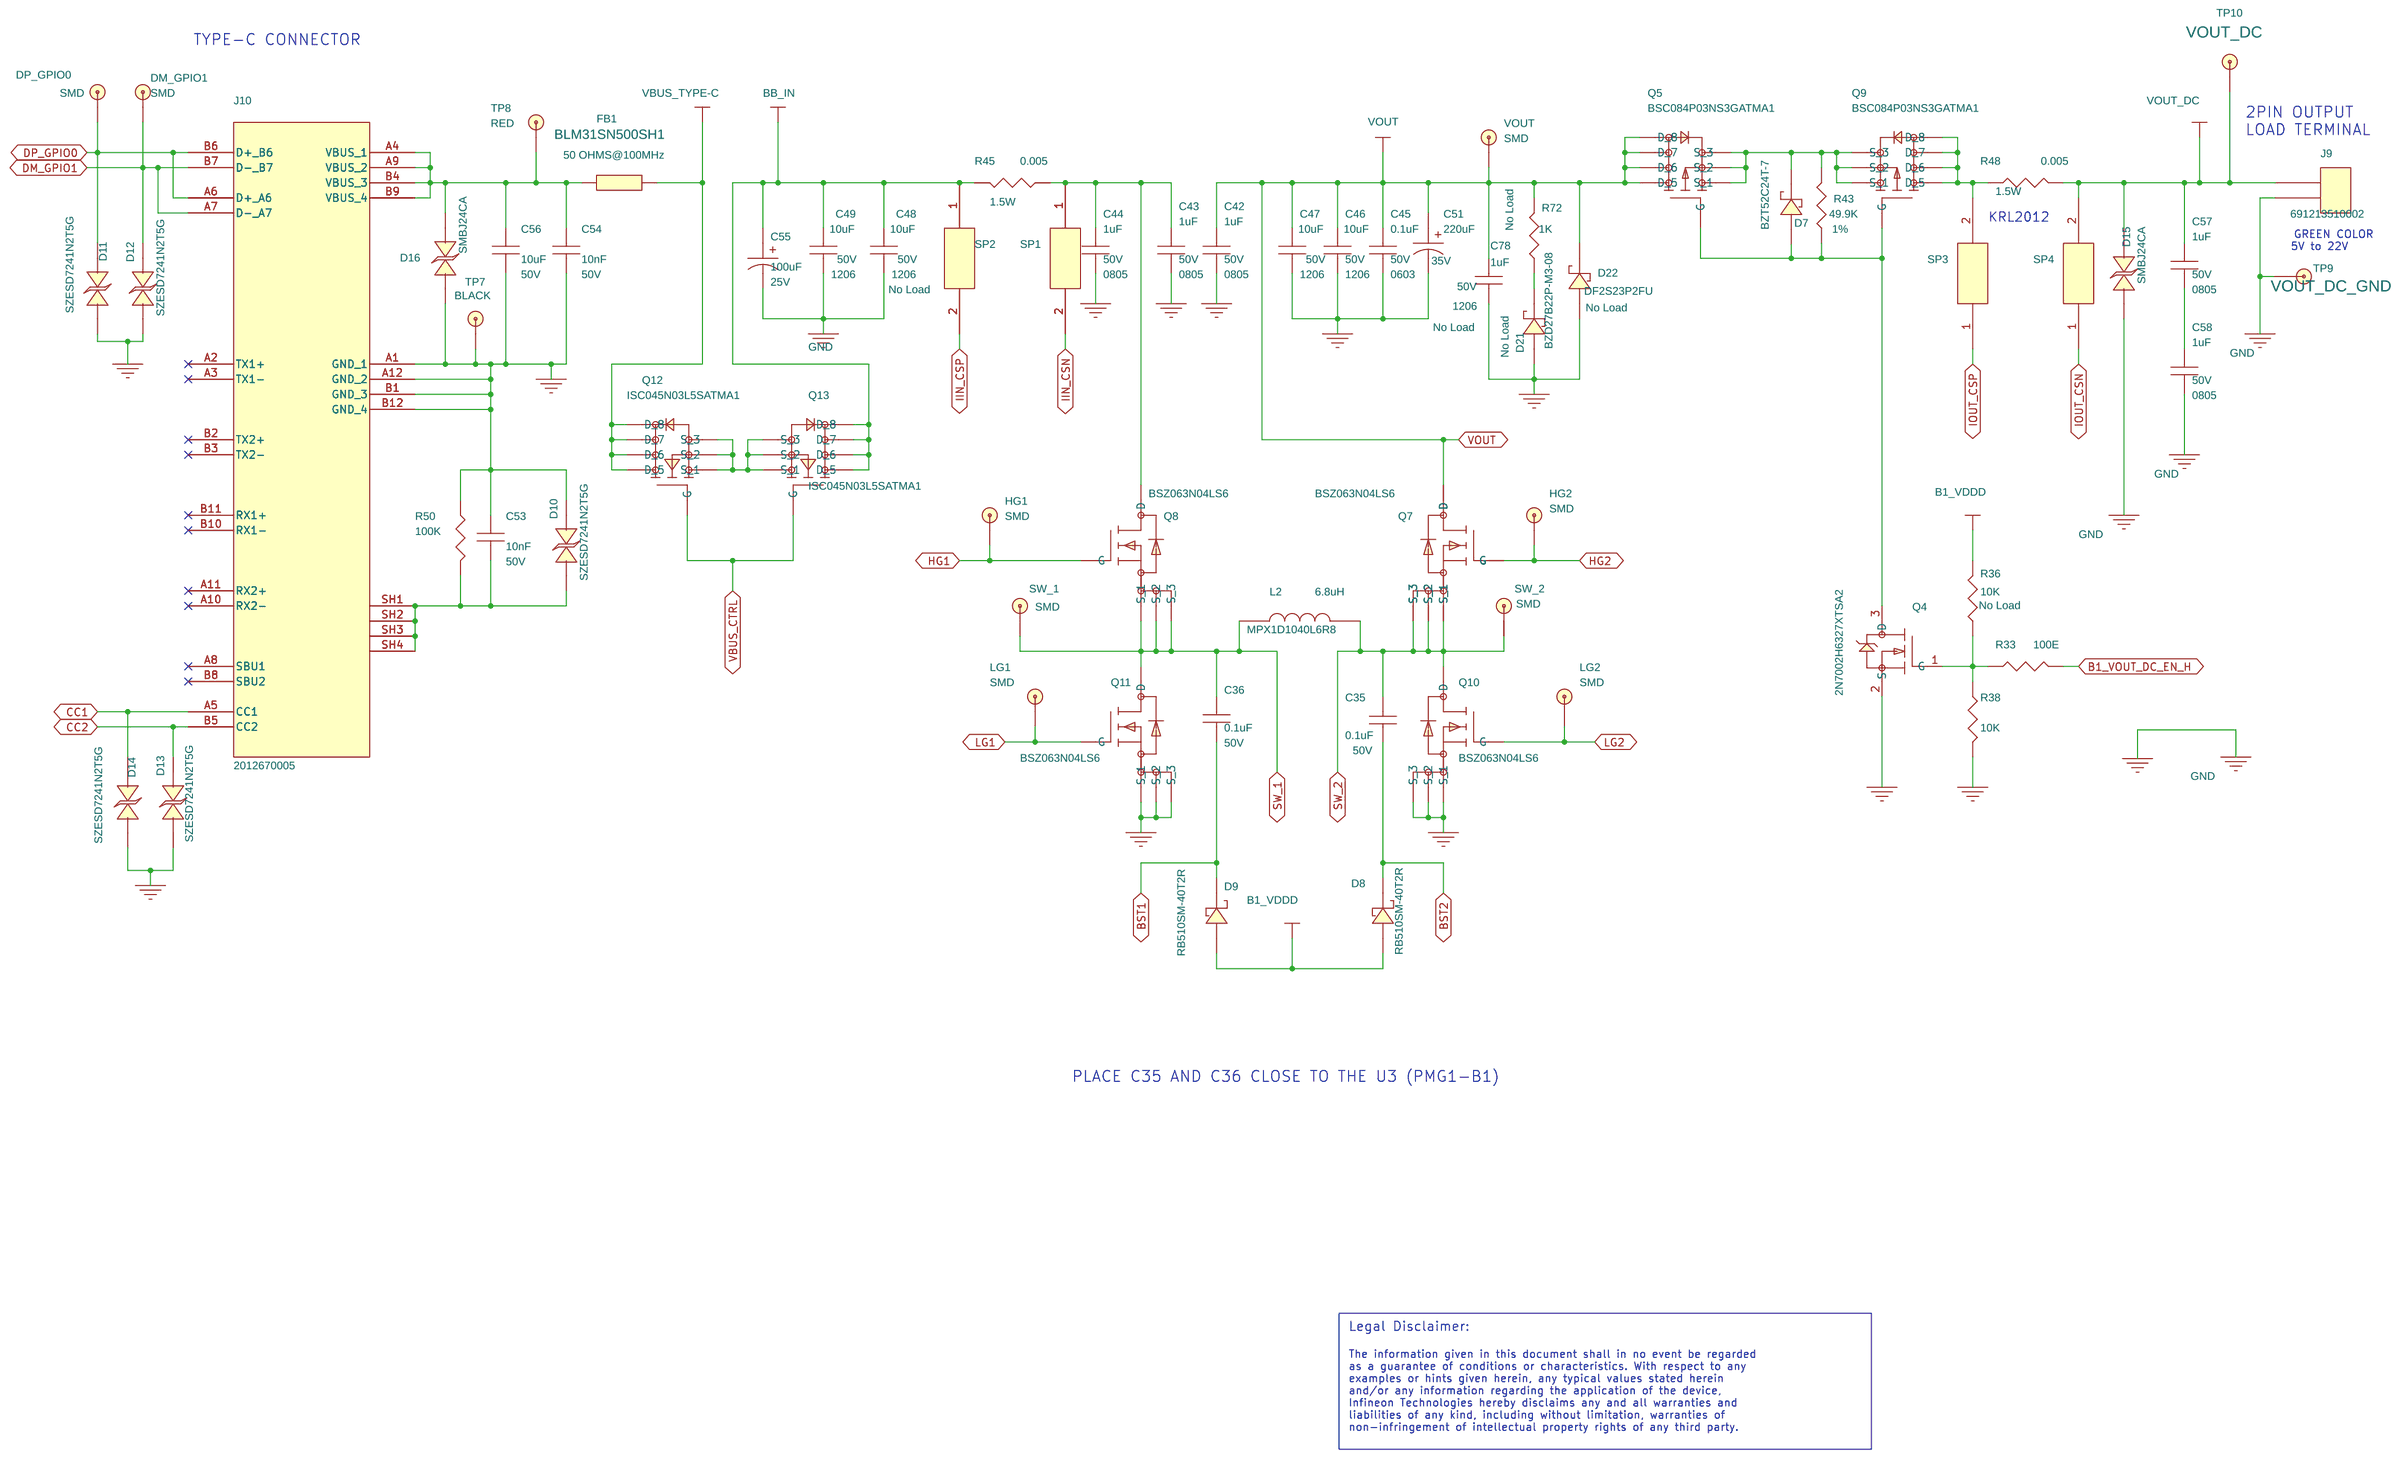
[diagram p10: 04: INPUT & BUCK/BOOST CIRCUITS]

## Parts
sheet 03: KITPROG3
C1  1.0 uF  [CAPC1005_0402N]
C2  1.0 uF  [CAPC1005_0402N]
C3  0.1uF  [CAPC1005_0402N]
C4  1.0 uF  [CAPC1005_0402N]
C5  1.0 uF  [CAPC1005_0402N]
C6  0.1uF  [CAPC1005_0402N]
C7  0.1uF  [CAPC1005_0402N]
C8  0.1uF  [CAPC1005_0402N]
C9  1.0 uF  [CAPC1005_0402N]
C10  1.0 uF  [CAPC1005_0402N]
C65  1.0 uF  [CAPC1005_0402N]
C66  1.0 uF  [CAPC1005_0402N]
C67  0.1uF  [CAPC1005_0402N]
C68  1.0 uF  [CAPC1005_0402N]
C69  1.0 uF  [CAPC1005_0402N]
C70  0.1uF  [CAPC1005_0402N]
C71  0.1uF  [CAPC1005_0402N]
C72  1.0 uF  [CAPC1005_0402N]
C73  0.1uF  [CAPC1005_0402N]
C74  10nF  [CAPC1005_0402N]
C76  1.0 uF  [CAPC1005_0402N]
C77  0.1uF  [CAPC1005_0402N]
D1  ESD131-B1-W0201  [ESD0201_CANTRON]
D2  ESD131-B1-W0201  [ESD0201_CANTRON]
D3  MMSZ5230C-E3-08  [SOD-123_DI]
D20  SMBJ24CA  [DIOM5336X262N]
J1  DX07S016JA3R1500  [JAE_DX07S016JA3R1500]
J2  5 PIN PROG  [WURTH_61300511121]
J3  CON 5x2  [SULLINS_PPPC052LFBN-RC]
JMP1  USB_Hold  [CON_RA_STIFF_850P_TYPEC]
LED1  AMBER LED  [LEDC1608_0603N]
LED2  AMBER LED  [LEDC1608_0603N]
Q1  BSS308PEH6327XTSA1  [SOT95P240X111-3N]
Q2  BSS308PEH6327XTSA1  [SOT95P240X111-3N]
Q3  BSS308PEH6327XTSA1  [SOT95P240X111-3N]
R1  30K  [RESC1005_0402M]
R2  15K  [RESC1005_0402M]
R3  1M  [RESC1005_0402M]
R4  4.7K  [RESC1005_0402M]
R5  1K  [RESC1005_0402M]
R6  10K  [RESC1005_0402M]
R7  49.9K  [RESC1005_0402M]
R8  49.9K  [RESC1005_0402M]
R9  100K  [RESC1005_0402M]
R61  2.2K  [RESC1005_0402M]
R62  0 OHM  [RESC1608_0603N]
R63  4.7K  [RESC1005_0402M]
R64  0ohm  [RESC1608_0603N]
R65  2M  [RESC1005_0402M]
R66  2.2K  [RESC1005_0402M]
R67  22E  [RESC1005_0402M]
R68  22E  [RESC1005_0402M]
R69  100K  [RESC1005_0402M]
R70  5.1K  [RESC1005_0402M]
R71  5.1K  [RESC1005_0402M]
SW1  434123025826  [SW_SKRPACE010]
U1  CY8C5868LTI-LP039  [QFN40P800X800X100-69M]
sheet 04: INPUT & BUCK/BOOST CIRCUITS
C35  0.1uF  [capc1608x90n_ty]
C36  0.1uF  [capc1608x90n_ty]
C42  1uF  [capc2012X70n_murata]
C43  1uF  [capc2012X70n_murata]
C44  1uF  [capc2012X70n_murata]
C45  0.1uF  [capc1608x90n_ty]
C46  10uF  [CAPC3216X180N_TDK]
C47  10uF  [CAPC3216X180N_TDK]
C48  10uF  [CAPC3216X180N_TDK]
C49  10uF  [CAPC3216X180N_TDK]
C51  220uF  [CAP_PC_10X12P4_WE]
C53  10nF  [CAPC1608X90N_A]
C54  10nF  [CAPC1608X90N_A]
C55  100uF  [cap_pc_6p30x8_ucc]
C56  10uF  [CAPC3216X190N_A]
C57  1uF  [capc2012X70n_murata]
C58  1uF  [capc2012X70n_murata]
C78  1uF  [capc2012X70n_murata]
D7  BZT52C24T-7  [BZT52C24T-7]
D8  RB510SM-40T2R  [SOD-523]
D9  RB510SM-40T2R  [SOD-523]
D10  SZESD7241N2T5G  [DIODFN100X60X45-2N]
D11  SZESD7241N2T5G  [DIODFN100X60X45-2N]
D12  SZESD7241N2T5G  [DIODFN100X60X45-2N]
D13  SZESD7241N2T5G  [DIODFN100X60X45-2N]
D14  SZESD7241N2T5G  [DIODFN100X60X45-2N]
D15  SMBJ24CA  [DIOM5336X262N]
D16  SMBJ24CA  [DIOM5336X262N]
D21  BZD27B22P-M3-08  [DO-219AB]
D22  DF2S23P2FU  [SOD-323]
DM_GPIO1  SMD  [SMDTP]
DP_GPIO0  SMD  [SMDTP]
FB1  50 OHMS@100MHz  [IND1206N]
HG1  SMD  [SMDTP]
HG2  SMD  [SMDTP]
J9  691213510002  [CONN_691213510002_WRE]
J10  2012670005  [MOLEX_2012670005]
L2  6.8uH  [MPX1D1040L6R8]
LG1  SMD  [SMDTP]
LG2  SMD  [SMDTP]
Q4  2N7002H6327XTSA2  [2N7002H6327XTSA2]
Q5  BSC084P03NS3GATMA1  [BSC030P03NS3]
Q7  BSZ063N04LS6  [BSZ063N04LS6]
Q8  BSZ063N04LS6  [BSZ063N04LS6]
Q9  BSC084P03NS3GATMA1  [BSC030P03NS3]
Q10  BSZ063N04LS6  [BSZ063N04LS6]
Q11  BSZ063N04LS6  [BSZ063N04LS6]
Q12  ISC045N03L5SATMA1  [IFX-PG-TDSON-8-6-V]
Q13  ISC045N03L5SATMA1  [IFX-PG-TDSON-8-6-V]
R33  100E  [resc1608x55n_pec]
R36  10K  [resc1608x55n_pec]
R38  10K  [resc1608x55n_pec]
R43  49.9K  [RESC1005X40N_PEC]
R45  0.005  [SUSUMU-KRL3216]
R48  0.005  [SUSUMU-KRL3216]
R50  100K  [resc1608x55n_pec]
R72  1K  [resc1608x55n_pec]
SP1  NetShort2  [NetShort2]
SP2  NetShort2  [NetShort2]
SP3  NetShort2  [NetShort2]
SP4  NetShort2  [NetShort2]
SW_1  SMD  [SMDTP]
SW_2  SMD  [SMDTP]
TP7  BLACK  [TP-43R_S_B]
TP8  RED  [tp-43r_s_r]
TP9  BLACK  [TP-43R_S_B]
TP10  RED  [tp-43r_s_r]
VOUT  SMD  [SMDTP]
sheet 05: PMG1-B1 CONTROLLER
C17  1uF  [capc1608x90n_ty]
C20  0.1uF  [capc1005x56n_cyps]
C21  0.1uF  [capc1005x56n_cyps]
C22  390pF  [capc1608x90n_ty]
C25  390pF  [capc1608x90n_ty]
C26  10uF  [capc2012X70n_murata]
C27  0.1uF  [capc1608x90n_ty]
C28  0.1uF  [capc1005x56n_cyps]
C29  0.1uF  [capc1005x56n_cyps]
C30  0.1uF  [capc1608x90n_ty]
C31  0.1uF  [capc1005x56n_cyps]
C34  0.1uF  [capc1608x90n_ty]
C37  1uF  [capc1608x90n_ty]
C38  0.1uF  [capc1608x90n_ty]
C39  100nF  [CAPC2012X70N_MURATA]
C52  1nF  [capc1005x56n_cyps]
C59  1nF  [capc1005x56n_cyps]
C75  0.1uF  [capc1005x56n_cyps]
D23  PLZ24B-G3/H  [DO-219AC]
NTC0  R, NTC  [resc1608x55n_pec]
NTC1  R, NTC  [resc1608x55n_pec]
NTCP0  SMD  [SMDTP]
NTCP1  SMD  [SMDTP]
R39  0E  [resc1608x55n_pec]
R40  0E  [resc1608x55n_pec]
R41  0E  [resc1608x55n_pec]
R42  100E  [resc1608x55n_pec]
R46  4.02K  [RESC1005X40N_PEC]
R47  0E  [resc1608x55n_pec]
R49  0E  [resc1608x55n_pec]
R51  4.02K  [RESC1005X40N_PEC]
TP4  SMD  [SMDTP]
TP6  SMD  [SMDTP]
U3  CYPM1116-48LQXI  [QFN40P600X600X60-49N]
sheet 06: INTERFACE SIGNALS
C12  0.1uF  [CAPC1005_0402N]
C13  0.1uF  [CAPC1005_0402N]
C14  0.1uF  [CAPC1608X90N_TY]
C15  22uF  [CAPC1608X90N_TY]
C23  0.1uF  [capc1005x56n_cyps]
C24  10uF  [capc2012_0805n]
D4  CMHSH5-4 TR PBFREE  [DIO2_SOD123N]
D5  CMHSH5-4 TR PBFREE  [DIO2_SOD123N]
D6  CMHSH5-4 TR PBFREE  [DIO2_SOD123N]
D17  CMHSH5-4 TR PBFREE  [DIO2_SOD123N]
D18  CMHSH5-4 TR PBFREE  [DIO2_SOD123N]
D19  CMHSH5-4 TR PBFREE  [DIO2_SOD123N]
LED3  GREEN  [LEDC1608X80N_G]
LED4  GREEN  [LEDC1608X80N_G]
R10  0 OHM  [RESC1608_0603N]
R11  0 OHM  [RESC1608_0603N]
R12  2.2K  [RESC1005_0402M]
R13  2.2K  [RESC1005_0402M]
R14  0OHM  [resc1005x40n_pec]
R17  0 OHM  [RESC1608_0603N]
R18  330E  [RESC1608X55N_A]
R19  4.7K  [RESC1005_0402M]
R20  4.7K  [RESC1005_0402M]
R21  0 OHM  [RESC1608_0603N]
R25  0 OHM  [RESC1608_0603N]
R26  0 OHM  [RESC1608_0603N]
R27  0E  [RESC1608_0603N]
R28  330E  [RESC1608X55N_A]
R30  0 OHM  [RESC1608_0603N]
R31  0 OHM  [RESC1608_0603N]
R32  0E  [RESC1608_0603N]
R34  2.2K  [RESC1608X55N_A]
R35  2.2K  [RESC1608X55N_A]
SW2  PTS810 SJG 250 SMTR LFS  [SW_SKRPACE010]
SW3  434123025826  [SW_SKRPACE010]
TP2  TP_SMD  [TP102C]
TP3  BLACK  [TP-43R_S_B]
TP5  TP_SMD  [TP102C]
U2  TLE42744EV50  [SOP65P500X400X170-15N]
sheet 07: CONNECTOR INTERFACES
C11  1uF  [capc1608x90n_ty]
J4  CON 5x2  [SULLINS_PPPC052LFBN-RC]
J6  TSW-112-14-G-S  [SAMTEC_TSW-112-14-G-S]
J7  TSW-112-14-G-S  [SAMTEC_TSW-112-14-G-S]
J8  50MIL KEYED SMD  [SAMTEC_FTSH-105-01-L-DV-K]
TVS1  ESD3V3D5-TP  [SODFL1608X77M]
sheet 08: SOURCE BUCK (27W MAX)
C16  10uF  [CAPC3216X180N_TDK]
C18  12pF  [capc1608x90n_ty]
C19  4.7uF  [capc2012X70n_murata]
C32  10uF  [CAPC3216X180N_TDK]
C33  10uF  [CAPC3216X180N_TDK]
C40  10uF  [CAPC3216X180N_TDK]
C41  100 pF  [capc1608x90n_ty]
C50  4.7uF  [capc2012X70n_murata]
C60  10uF  [CAPC3216X180N_TDK]
C61  0.1uF  [capc1608x90n_ty]
C62  1.2nF  [capc1608x90n_ty]
C63  4.7uF  [capc2012X70n_murata]
C64  4.7uF  [capc2012X70n_murata]
C90  10uF  [CAPC3216X180N_TDK]
J11  691103110002  [TE_1776275-2]
L1  15uH  [IND_XGL6060-682MEC_COC-M]
Q6  BSZ0589NSATMA1  [PG-TSDSON-8-33]
Q14  2N7002H6327XTSA2  [sot23_1_2_3]
R15  10K  [resc1608x55n_pec]
R16  10K  [resc1608x55n_pec]
R22  0E  [resc1608x55n_pec]
R29  165K  [resc1608x55n_pec]
R44  0E  [resc1608x55n_pec]
R52  0E  [resc1608x55n_pec]
R53  39 OHM  [resc1608x55n_pec]
R54  0E  [resc1608x55n_pec]
R55  10K  [resc1608x55n_pec]
R56  34K  [resc1608x55n_pec]
R57  12pF  [resc1608x55n_pec]
R58  0603  [resc1608x55n_pec]
R59  34K  [resc1608x55n_pec]
R60  30K  [resc1608x55n_pec]
U4  STELPD01PUR  [DFN50P300X300X100-11N_B]
U5  AP63357  [DFN45P200X300X85-9L]
sheet 09: BATTERY CELL & TEMPERATURE
C79  10nF  [capc1608x90n_ty]
C80  10nF  [capc1608x90n_ty]
C81  10nF  [capc1608x90n_ty]
C82  10nF  [capc1608x90n_ty]
C83  10nF  [capc1608x90n_ty]
C84  0.1uF  [capc1608x90n_ty]
C85  0.1uF  [capc3216x180n_tdk]
C86  0.1uF  [capc3216x180n_tdk]
C87  0.1uF  [capc3216x180n_tdk]
C88  0.1uF  [capc3216x180n_tdk]
C89  0.1uF  [capc3216x180n_tdk]
J13  61300611121  [BERG_2p54P_1X6N]
R73  12K  [resc1608x55n_pec]
R74  10K  [resc1608x55n_pec]
R75  34K  [resc1608x55n_pec]
R76  10K  [resc1608x55n_pec]
R77  56K  [resc1608x55n_pec]
R78  10K  [resc1608x55n_pec]
R79  78.7K  [resc1608x55n_pec]
R80  10K  [resc1608x55n_pec]
R81  100K  [resc1608x55n_pec]
R82  10K  [resc1608x55n_pec]
R83  6.65K  [resc1608x55n_pec]
R84  1K  [resc1608x55n_pec]
R85  953E  [resc1608x55n_pec]
R86  1K  [resc1608x55n_pec]
R87  1K  [resc1608x55n_pec]
R88  1K  [resc1608x55n_pec]
R89  1K  [resc1608x55n_pec]
R90  1K  [resc1608x55n_pec]
SW4  CAS-120TA  [CAS-120A]
SW5  CAS-120TA  [CAS-120A]
SW6  CAS-120TA  [CAS-120A]
SW7  CAS-120TA  [CAS-120A]
SW8  CAS-120TA  [CAS-120A]
TP11  SMD  [SMDTP]
sheet 10: ACCESSORIES
ACC1  LBL PCA Label  [-NA-]
ACC2  SJ61A6  [SJ61A6]
ACC3  SJ61A6  [SJ61A6]
ACC4  SJ61A6  [SJ61A6]
ACC5  SJ61A6  [SJ61A6]
ACC8  SJ61A6  [SJ61A6]
ACC9  SJ61A6  [SJ61A6]
ACC10  SJ61A6  [SJ61A6]
PCB  600-60657-01  [EVAL_PMG1_B1_DRP_Kit]

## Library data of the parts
C1 C2 C4 C5 C10 C65 C66 C68 C72 = CAPACITOR_NON-POL: CAP CER 1UF 10V X5R 0402; Manufacturer: Wurth
C3 C6-C8 C70 C71 C73 = CAPACITOR_NON-POL: CAP, CER, 0.1UF, 10%, X7R, 16V, 0402; Manufacturer: Wurth; Tolerance: 10%
C9 C76 = CAPACITOR_NON-POL: CAP CER 1UF 10V X5R 0402; MFG Part number: 885012105012; Manufacturer: Wurth
C67 C77 = CAPACITOR_NON-POL: CAP, CER, 0.1UF, 10%, X7R, 16V, 0402; MFG Part number: 885012205037; Manufacturer: Wurth; Tolerance: 10%
C69 = CAPACITOR_NON-POL: CAP CER 1UF 10V X5R 0402; Asm_Instruction: No Load; Manufacturer: Wurth
C74 = CAPACITOR_NON-POL: CAP, CER, 10nF, 10%, X7R, 50V, 0402; Manufacturer: Wurth
D1 D2 = BZX84C18_SOT_1: 13V Clamp 3.5A (8/20µs) Ipp Tvs Diode Surface Mount WLL-2-3; Manufacturer: Infineon Technologies; VOLTAGE: +/-20KV
D3 = DIO-ZENER_3: ZENER SOD-123 4.7V 0.5W 2%; Manufacturer: Vishay Semiconductors
D15 D16 D20 = DIODE_TVS_BI-DIR: TVS DIODE 24V 38.9V DO214AA; Manufacturer: Littelfuse Inc.
J1 = USB_MICRO_R_A_DIP_5: CONN RCP USB2.0 TYP C 24P SMD RA; Manufacturer: JAE Electronics
J2 = HEADER_5_0: 1X5 Firmware provision; Asm_Instruction: No Load; MFG Part number: 61300511121; Manufacturer: centronic precision
J3 J4 = RECPT_4X2_100MIL_5: CONN, HEADER, FEMALE, 2.54mm, DOUBLE, GOLD, 10POS, TH; Asm_Instruction: No Load; Manufacturer: Sullins Connector Solutions
JMP1 = USB_JUMP_0: WIRE, WIRE BUS BAR 1000' LONG, THICKNESS 22 AWG; Asm_Instruction: No Load; Manufacturer: Alpha Wire
LED1 LED2 = LED_2: LED, YELLOW, CLEAR, 0603; Manufacturer: Wurth
Q1-Q3 = FET-MOS-P_1: MOSFET P-CH 30V 2A SOT23-3; Manufacturer: Infineon Technologies
R1 = RESISTOR: RES, 30K OHM, 1/10W, 5%, 0402, SMD; Manufacturer: Panasonic
R2 = RESISTOR: RES, 15K OHM, 1/10W, 5%, 0402, SMD; Manufacturer: Panasonic
R3 = RESISTOR: RES 1M OHM 1% 1/16W 0402; Manufacturer: Vishay Dale
R4 R63 = RESISTOR: RES, 4.7K OHM, 5%, 100PPM, 1/16W, 0402; Asm_Instruction: No Load; Manufacturer: Yageo; Tolerance: 5%
R5 = RES: RES SMD 1K OHM 1% 1/5W 0402; Manufacturer: Vishay Dale; Tolerance: 1%
R6 = RES: RES, 10K, 5%, 1/10W, 0402; Manufacturer: Panasonic; Tolerance: 5%
R7 = RESISTOR: RES, 49.9K OHM, 1%, 100PPM, 1/10W, 0402, SMD; Asm_Instruction: No Load; Manufacturer: Panasonic
R8 = RESISTOR: RES, 49.9K OHM, 1%, 100PPM, 1/10W, 0402, SMD; Manufacturer: Panasonic
R9 = RESISTOR: RES, 100K OHM, 5%, 100PPM, 1/16W, 0402; Manufacturer: Yageo; Tolerance: 5%
R61 R66 = RESISTOR: RES, 2.2K OHM, 5%, 200PPM, 1/10W, 0402; Manufacturer: Panasonic; Tolerance: 5%
R62 = RES: RES, 0 OHM, JUMPER, 1A, 0603; Asm_Instruction: No Load; Manufacturer: Panasonic; Tolerance: JUMPER
R64 = RESISTOR: RES, 0.0OHM, 1/10W, 0603, SMD; Manufacturer: Rohm Semiconductor
R65 = RESISTOR: RES 2M OHM 1% 1/16W 0402; Manufacturer: Vishay Dale
R67 R68 = RESISTOR: RES, 22 OHM, 1%, 100PPM, 1/16W, 0402; Manufacturer: Yageo
R69 = RESISTOR: RES, 100K OHM, 5%, 100PPM, 1/16W, 0402; Manufacturer: Yageo
R70 R71 = RES: RES SMD 5.1K OHM 1% 1/16W 0402; Manufacturer: Yageo; Tolerance: 1%
SW1 SW3 = SW_PUSH_NO_4-PIN: SW, TACTILE SWITCH, 4.2x3.2x2.5MM, 260GF; Manufacturer: Wurth
U1 = CY8C38***-QFN68_0: IC MCU 32BIT 256KB FLASH 68QFN; Manufacturer: Cypress Semiconductor
C30 C34-C36 C38 = CAP: CAP CER 0.1UF 50V X7R 0603; MFG Part number: 885012206095; Manufacturer: Würth Elektronik; Tolerance: 10%; Voltage: 50V
C42-C44 C57 C58 = CAP: CAP CER 1UF 50V X7R 0805; MFG Part number: 885012207103; Manufacturer: Würth Elektronik; Package Size: 0805; Voltage: 50V
C45 C61 = CAP: CAP CER 0.1UF 50V X7R 0603; MFG Part number: 885012206095; Manufacturer: Würth Elektronik; Package Size: 0603; Tolerance: 10%; Voltage: 50V
C46 C47 C49 = CAP: CAP CER 10UF 50V X7R 1206; MFG Part number: CL31B106KBHNNNE; Manufacturer: Samsung Electro-Mechanics; Package Size: 1206; Voltage: 50V
C48 = CAP: CAP CER 10UF 50V X7R 1206; Asm_Instruction: No Load; MFG Part number: CL31B106KBHNNNE; Manufacturer: Samsung Electro-Mechanics; Package Size: 1206; Voltage: 50V
C51 = CAP_P_ALT: CAP ALUM POLY 220UF 20% 35V SMD; MFG Part number: 875075661008; Manufacturer: Würth Elektronik; Tolerance: 20%; Voltage: 35V
C53 C54 = CAP: CAP CER 10000PF 50V X7R 0603; MFG Part number: 885012206089; Manufacturer: Würth Elektronik; Voltage: 50V
C55 = CAP_P_ALT: CAP ALUM HYBRD 100UF 20% 25V SMD; MFG Part number: HHXE250ARA101MF80G; Manufacturer: United Chemi-Con; Tolerance: 20%; Voltage: 25V
C56 = CAP: CAP CER 10UF 50V X7T 1206; MFG Part number: GRM31CD71H106KE11L; Manufacturer: Murata Electronics; Voltage: 50V
C78 = CAP: CAP CER 10UF 50V X7R 1206; Asm_Instruction: No Load; MFG Part number: 885012207103; Manufacturer: Würth Elektronik; Package Size: 1206; Voltage: 50V
D7 = DIODE_SCHOTTKY_5: DIODE ZENER 24V 300MW SOD523; Manufacturer: Diodes Incorporated
D8 = DIODE_SCHOTTKY_5: DIODE SCHOTTKY 40V 100MA EMD2; Manufacturer: Rohm Semiconductor
D9 = DIODE_SCHOTTKY_4: DIODE SCHOTTKY 40V 100MA EMD2; Manufacturer: Rohm Semiconductor
D10-D14 = DIODE_TVS_BI-DIR: TVS DIODE 24V 48V 2X2DFN; Manufacturer: ON Semiconductor
D21 = DIODE_SCHOTTKY_1: DIODE ZENER 22V 800MW DO219AB; Asm_Instruction: No Load; Manufacturer: Vishay General Semiconductor - Diodes Division
D22 = DIODE_SCHOTTKY_0: TVS DIODE 21VWM 27.3VC USC; Asm_Instruction: No Load; MFG Part number: DF2S23P2FU-H3F; Manufacturer: Diodes Incorporated
DM_GPIO1 DP_GPIO0 HG1 HG2 LG1 LG2 NTCP0 NTCP1 SW_1 SW_2 TP4 TP6 = TEST_POINT
FB1 = FERRITEBEAD_ALT1: Ferrite Beads 1206 50ohms 12A DCR=.0016ohm AutoPWR, AEC-Q200; MFG Part number: BLM31SN500SH1; Manufacturer: Murata Electronics
J9 = CON2: TERM BLK 2P SIDE ENT 5.08MM PCB GREEN COLOR; Manufacturer: Würth Elektronik
J10 = USB-PD_TYPE-C_1: USB-C (USB TYPE-C) USB 3.1 (USB 3.1 Gen 2, Superspeed+) Receptacle Connector 24 Position Surface Mount, Right Angle; Through Hole; Manufacturer: Molex
L2 = XAL1010-472ME: 6.8 µH Shielded Drum Core, Wirewound Inductor 8.3 A 24.1mOhm Max Nonstandard -; Manufacturer: KEMET
Q4 = 2N7002H6327XTSA2_0: MOSFET N-CH 60V 300MA SOT23-3; Manufacturer: Infineon Technologies
Q5 Q9 = MOSFET_P_SO8: MOSFET P-CH 30V 14.9A 8TDSON; Manufacturer: Infineon Technologies
Q7 Q8 Q10 Q11 = 5P_N-CH_TYPE1C: MOSFET N-CH 40V 15A/40A TSDSON; MFG Part number: BSZ063N04LS6ATMA1; Manufacturer: Infineon Technologies
Q12 Q13 = MOSFET_P_SO8_0: MOSFET N-CH 30V 18A/63A TDSON; Manufacturer: Infineon Technologies
R33 = RES: RES 100 OHM 1% 1/5W 0603; MFG Part number: SR0603FR-7W100RL; Manufacturer: YAGEO; Tolerance: 1%; Wattage: 0.2W
R36 R72 = RES: RES 10K OHM 1% 1/10W 0603; Asm_Instruction: No Load; MFG Part number: RMCF0603FT10K0; Manufacturer: Stackpole Electronics Inc; Tolerance: 1%; Wattage: 0.125W
R38 = RES: RES 10K OHM 1% 1/10W 0603; MFG Part number: RMCF0603FT10K0; Manufacturer: Stackpole Electronics Inc; Tolerance: 1%; Wattage: 0.125W
R43 = R: RES 49.9K OHM 1% 1/16W 0402; MFG Part number: RMCF0402FT49K9; Manufacturer: Stackpole Electronics Inc; Tolerance: 1%; Wattage: 1/16W
R45 R48 = RES: RES.,0.005 OHM,1%,1.5W,1206,LONG-SIDE TERM,KRL3216,METAL,SENSE,AEC-Q200; MFG Part number: KRL3216E-C-R005-F-T1; Manufacturer: SUSUMU; Tolerance: 1%; Wattage: 1.5W
R50 = RES: RES 100K OHM 1% 1/10W 0603; MFG Part number: RC0603FR-07100KL; Manufacturer: YAGEO; Wattage: 0.125W
SP1-SP4 = NetShort2
TP7 = TEST_POINT: TEST POINT PC MINI .040"D BLACK; MFG Part number: 5001; Manufacturer: KEYSTONE ELECTRONICS
TP8 = TEST_POINT: TEST POINT PC MINI .040"D RED; MFG Part number: 5000; Manufacturer: KEYSTONE ELECTRONICS
TP9 = TEST_POINT: TEST POINT PC MINI .040"D BLACK; MFG Part number: 5001; Manufacturer: KEYSTONE ELECTRONICS; PART_FIELD_1: VOUT_DC_GND
TP10 = TEST_POINT: TEST POINT PC MINI .040"D RED; MFG Part number: 5000; Manufacturer: KEYSTONE ELECTRONICS; PART_FIELD_1: VOUT_DC
VOUT = TEST_POINT: Asm_Instruction: No Load
C17 = 0_0.01uF-50V-10%-X7R-0603: CAP CER 1UF 25V X7R 0603; MFG Part number: 885012206076; Manufacturer: Würth Elektronik; Voltage: 25V
C20 C28 C29 C31 C75 = CAP: CAP CER 0.1UF 50V X7R 0402; MFG Part number: GCM155R71H104KE02J; Manufacturer: Murata Electronics; Tolerance: 10%; Voltage: 50V
C21 = CAP: CAP CER 0.1UF 50V X7R 0402; Asm_Instruction: No Load; MFG Part number: GCM155R71H104KE02J; Manufacturer: Murata Electronics; Tolerance: 10%; Voltage: 50V
C22 C25 = CAP: CAP CER 390PF 50V C0G/NPO 0603; MFG Part number: CC0603JRNPO9BN391; Manufacturer: Yageo; Tolerance: 10%; Voltage: 50V
C26 = CAP: CAP CER 10UF 10V X7R 0805; MFG Part number: GRM21BR71A106KA73K; Manufacturer: Murata Electronics; Voltage: 10V
C27 = CAP: CAP CER 0.1UF 50V X7R 0603; Asm_Instruction: No Load; MFG Part number: 885012206095; Manufacturer: Würth Elektronik; Tolerance: 10%; Voltage: 50V
C37 = CAP: CAP CER 1UF 25V X7R 0603; MFG Part number: 885012206076; Manufacturer: Würth Elektronik; Voltage: 25V
C39 = CAP: CAP CER 0.1UF 25V X7R 0805 AEC-Q200; MFG Part number: C0805C104K3RACAUTO; Manufacturer: KEMET; Tolerance: 10%; Voltage: 25V
C52 C59 = CAP: CAP CER 1000PF 50V X7R 0402; MFG Part number: 885012205061; Manufacturer: Würth Elektronik; Voltage: 50V
D23 = DIODE_SCHOTTKY_3: DIODE ZENER 23.19V 500MW DO219AC; MFG Part number: PLZ24B-G3_H; Manufacturer: Vishay General Semiconductor - Diodes Division
NTC0 NTC1 = RESISTOR_VAR_2: THERM NTC 100KOHM 4419K 0603; MFG Part number: NTCG164KF104FTDS; Manufacturer: TDK Corporation
R39 R40 = R: RES 0 OHM JUMPER 1/10W 0603; MFG Part number: RMCF0603ZT0R00; Manufacturer: YAGEO
R41 = R: RES 0 OHM JUMPER 1/4W 0603; MFG Part number: HCJ0603ZT0R00; Manufacturer: Stackpole Electronics Inc
R42 = RES: RES 100 OHM 1% 1/5W 0603; MFG Part number: SR0603FR-7W100RL; Manufacturer: YAGEO; Tolerance: 1%
R46 = RES: RES SMD 4.02K OHM 1% 1/10W 0402; MFG Part number: ERJ-2RKF4021X; Manufacturer: MERITEK; Tolerance: 1%
R47 R49 = RES: RES 0 OHM JUMPER 1/10W 0603; MFG Part number: RMCF0603ZT0R00; Manufacturer: YAGEO; Tolerance: 1%
R51 = RES: RES SMD 4.02K OHM 1% 1/10W 0402; MFG Part number: ERJ-2RKF4021X; Manufacturer: Panasonic Electronic Components; Tolerance: 1%
U3 = PMG1-B1_17: PMG1-B1 controller 48 pin QFN; Manufacturer: Infineon Technologies
C12 C13 = CAPACITOR_NON-POL: CAP, CER, 0.1UF, 10%, X7R, 16V, 0402; Asm_Instruction: No Load; Manufacturer: Samsung Electro-Mechanics America, Inc.
C14 = CAPACITOR_NON-POL: CAP CER 0.1UF 6.3V X7R 0603; Manufacturer: KEMET
C15 = C_np: CAP CER 22UF 6.3V X5R 0603; Manufacturer: Murata Electronics
C23 = CAP_NP: CAP CER 0.1UF 50V X7R 0402; Manufacturer: AVX Corporation
C24 = CAPACITOR_NON-POL: CAP CER 10UF 50V X5R 0805; Manufacturer: Murata Electronics
D4-D6 D17-D19 = DIO_STKY_PMEG3020_0: DIODE SCHOTTKY 40V 500MA SOD123; Manufacturer: Central Semiconductor Corp
LED3 = LED_GREEN2_0603: LED GREENCLEAR 0603 SMD; MFG Part number: LTST-C190GKT; Manufacturer: Lite-On Inc.
LED4 = LED_GREEN2_0603: LED GREENCLEAR 0603 SMD; Manufacturer: Lite-On Inc.
R10 R11 R17 R21 R25 R26 R30 R31 = RES: RES, 0 OHM, JUMPER, 1A, 0603; Manufacturer: Panasonic
R12 = RESISTOR: RES, 2.2K OHM, 5%, 200PPM, 1/10W, 0402; Asm_Instruction: No Load; Manufacturer: Panasonic
R13 = RESISTOR: RES, 2.2K OHM, 5%, 200PPM, 1/10W, 0402; Asm_Instruction: No Load; Manufacturer: MERITEK
R14 = R: RES SMD 0 OHM JUMPER 1/16W 0402; Manufacturer: Yageo
R18 R28 = RESD,0402,5%,1_32W,10K: Manufacturer: Yageo; PART_NUMBER: RC0603JR-07330RL
R19 = RESISTOR: RES, 4.7K OHM, 5%, 100PPM, 1/16W, 0402; Asm_Instruction: No Load; MFG Part number: RC0402JR-074K7L; Manufacturer: Yageo
R20 = RESISTOR: RES, 4.7K OHM, 5%, 100PPM, 1/16W, 0402; Asm_Instruction: No Load; Manufacturer: Yageo
R27 R32 = R: RES SMD 0 OHM JUMPER 1/10W 0603; Manufacturer: Yageo
R34 R35 = RESD,0402,5%,1_32W,10K: Manufacturer: Stackpole Electronics Inc
SW2 = SW_PUSH_NO_4-PIN: SWITCH TACTILE SPST-NO 0.05A 16V; Manufacturer: C&K
TP2 TP5 = TEST_POINT: TESTPOINT, SMD, 40MILS, ROUND; Asm_Instruction: No Load; Manufacturer: -NA-
TP3 = TEST_POINT: TEST POINT PC MINI .040"D RED; Manufacturer: Keystone Electronics
U2 = TLE42744EV50
C11 = CAP-NP_0: CAP CER 1UF 16V X7R 0603; Asm_Instruction: No Load; Manufacturer: KEMET; Tolerance: 10%; Voltage: 16V
J6 J7 = HEADER_12_0: Asm_Instruction: No Load
J8 = 10_Pin_Header_50mil_Keyed_SMD: CONN, HEADER, 10POS, .05", DL, SMD; Asm_Instruction: No Load; Manufacturer: Samtec
TVS1 = TVS_5V_SOD-323_0: DIO, TVS, UNIDIR, 158W, 3.3V, SOD-523; Asm_Instruction: No Load; Manufacturer: Micro Commercial Co
C16 C90 = CAP: 10 µF ±10% 35V Ceramic Capacitor X7R 1206 (3216 Metric); Asm_Instruction: No Load; MFG Part number: C3216X7R1V106K160AE; Manufacturer: TDK Corporation; Package Size: 1206
C18 = CAP: CAP CER 12PF 100V C0G/NP0 0603; MFG Part number: C0603C120K1GAC7867; Manufacturer: KEMET; Package Size: 0603
C19 C63 C64 = CAP: 4.7 µF ±10% 50V Ceramic Capacitor X7R 0805 (2012 Metric); MFG Part number: GRM21BZ71H475KE15K; Manufacturer: Murata Electronics; Package Size: 0805; Voltage: 50V
C32 C33 C40 C60 = CAP: 10 µF ±10% 35V Ceramic Capacitor X7R 1206 (3216 Metric); MFG Part number: C3216X7R1V106K160AE; Manufacturer: TDK Corporation; Package Size: 1206; Voltage: 35V
C41 = CAP: CAP CER 100PF 50V C0G/NP0 0603; MFG Part number: 885012006057; Manufacturer: Würth Elektronik; Package Size: 0603; Tolerance: ±5%; Voltage: 50V
C50 = CAP: 4.7 µF ±10% 50V Ceramic Capacitor X7R 0805 (2012 Metric); Asm_Instruction: No Load; MFG Part number: GRM21BZ71H475KE15K; Manufacturer: Murata Electronics; Package Size: 0805
C62 = CAP: CAP CER 1200PF 50V X7R 0603; MFG Part number: C0603C122K5RAC7867; Manufacturer: KEMET; Package Size: 0603
J11 = CON2: TERM BLK 2POS SIDE ENT 3.5MM PCB; Manufacturer: Würth Elektronik
L1 = XAL1010-472ME: Shielded Power Inductors, 15 uH, Isat 5.8 A (30%), Irms 5.4 A, SRF 11 MHz, DCR: 28.2 mOhm; MFG Part number: XGL6060-153ME; Manufacturer: Coilcraft
Q6 = BSC059N04LS_G_0: MOSFET N-CH 30V 17A TSDSON; Manufacturer: Infineon Technologies
Q14 = 2N7002H6327XTSA2: MOSFET N-CH 60V 300MA SOT23-3; Manufacturer: Infineon Technologies
R15 = RES: RES 10K OHM 1% 1/10W 0603; Asm_Instruction: No Load; MFG Part number: RMCF0603FT10K0; Manufacturer: Stackpole Electronics Inc; Package Size: 0603; Tolerance: 1%
R16 R55 = RES: RES 10K OHM 1% 1/10W 0603; MFG Part number: RMCF0603FT10K0; Manufacturer: Stackpole Electronics Inc; Package Size: 0603; Tolerance: 1%
R22 R44 R52 = RES: RES 0 OHM JUMPER 1/10W 0603; MFG Part number: RMCF0603ZT0R00; Manufacturer: Stackpole Electronics Inc; Package Size: 0603
R29 = RES: RES SMD 162K OHM 0.1% 1/16W 0603; MFG Part number: RN73C1J165KBTD; Manufacturer: TE Connectivity Passive Product; Package Size: 0603; Tolerance: 0.1%
R53 = RES: RES SMD 39 OHM 1% 1/10W 0603; MFG Part number: RT0603FRE0739RL; Manufacturer: YAGEO; Package Size: 0603; Tolerance: 1%
R54 = RES: RES 0 OHM JUMPER 1/10W 0603; Asm_Instruction: No Load; MFG Part number: RMCF0603ZT0R00; Manufacturer: Stackpole Electronics Inc; Package Size: 0603
R56 = RES: RES 59K OHM 1% 1/10W 0603; MFG Part number: CRCW060359K0FKEAC; Manufacturer: Vishay Dale; Package Size: 0603
R57 = RES: CAP CER 12PF 100V C0G/NP0 0603; MFG Part number: C0603C120K1GAC7867; Manufacturer: KEMET; Package Size: 0603
R58 = RES: RES 0 OHM JUMPER 1/10W 0603; Asm_Instruction: No Load; MFG Part number: RC0603JR-070RP; Manufacturer: Stackpole Electronics Inc
R59 = RES: RES SMD 34K OHM 0.1% 1/10W 0603; MFG Part number: ERA-3AEB3402V; Manufacturer: Panasonic Electronic Components; Package Size: 0603; Tolerance: 0.11%
R60 = RES: 30 kOhms ±0.1% 0.1W, 1/10W Chip Resistor 0603 (1608 Metric) Automotive AEC-Q200 Thin Film; MFG Part number: ERA-3AEB303V; Manufacturer: Panasonic Electronic Components; Package Size: 0603; Tolerance: 0.1%
U4 = STELPD01PUR: ELECTRONIC SWITCH FOR POWER LINE; Manufacturer: STMicroelectronics
U5 = AP63357_1: 3.8V TO 32V INPUT, 3.5A LOW IQ SYNCHRONOUS BUCK; Manufacturer: Diodes Incorporated
C79-C83 = CAP: CAP CER 10000PF 50V X7R 0603; MFG Part number: 06035C103KAT2A; Manufacturer: KYOCERA AVX
C84 = 0_0.01uF-50V-10%-X7R-0603: CAP CER 0.1UF 50V X7R 0603; MFG Part number: 885012206095; Manufacturer: Würth Elektronik
C85-C89 = CAP: CAP CER 0.1UF 50V X7R 1206; MFG Part number: 885012208087; Manufacturer: Würth Elektronik; Tolerance: 10%
J13 = CON6: CONN HEADER VERT 6POS 2.54MM; Manufacturer: Würth Elektronik
R73 = RES: RES SMD 12K OHM 1% 1/10W 0603; MFG Part number: ERJ-3EKF1202V; Manufacturer: Panasonic Electronic Components; Tolerance: 1%
R74 R76 R78 R80 R82 = RES: RES 10K OHM 1% 1/10W 0603; MFG Part number: RMCF0603FT10K0; Manufacturer: Stackpole Electronics Inc; Tolerance: 1%
R75 = RES: RES 34K OHM 1% 1/10W 0603; MFG Part number: RC0603FR-0734KL; Manufacturer: YAGEO; Tolerance: 1%
R77 = RES: RES 56K OHM 1% 1/10W 0603; MFG Part number: RC0603FR-0756KL; Manufacturer: YAGEO
R79 = RES: RES SMD 78.7K OHM 1% 1/10W 0603; MFG Part number: AC0603FR-0778K7L; Manufacturer: YAGEO; Tolerance: 1%
R81 = RES: RES 100K OHM 1% 1/10W 0603; MFG Part number: RC0603FR-07100KL; Manufacturer: YAGEO
R83 = RES: RES SMD 6.65K OHM 1% 1/10W 0603; MFG Part number: ERJ-3EKF6651V; Manufacturer: Panasonic Electronic Components; Tolerance: 1%
R84 R86-R90 = RES: RES SMD 1K OHM 1% 1/10W 0603; MFG Part number: ERJ-3EKF1001V; Manufacturer: Panasonic Electronic Components; Tolerance: 1%
R85 = RES: RES 953 OHM 1% 1/10W 0603; MFG Part number: RC0603FR-07953RL; Manufacturer: Yageo; Tolerance: 1%
SW4-SW8 = SW_T_SPDT_1: SWITCH SLIDE SPDT 100MA 6V; Manufacturer: Nidec Copal Electronics
TP11 = TEST_POINT: Asm_Instruction: NO_Load
ACC1 = LBL_PCA_Label: LBL, PCA Label, Vendor Code, Datecode, Serial Number (YYWWVVXXXXX); Manufacturer: JETech
ACC2-ACC5 ACC8-ACC10 = SJ61A4: Bumper Cylindrical, Tapered 0.312" Dia (7.92mm) Polyurethane Black,5.4mm high; Manufacturer: 3M
PCB = PCB_PART_NUMBER: Manufacturer: Infineon Technologies

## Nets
5V: J6.1 R20.1 R27.1 R28.1 TP2.1
GND: C1.2 C2.2 C3.2 C4.2 C5.2 C6.2 C7.2 C8.2 C9.2 C10.2 C11.1 C12.1 C13.1 C14.2 C15.2 C16.2 C17.2 C19.2 C20.1 C21.2 C22.2 C23.1 C24.1 C25.2 C26.2 C28.1 C29.1 C30.2 C31.1 C32.2 C33.2 C34.2 C37.2 C38.2 C39.2 C40.2 C41.2 C42.2 C43.2 C44.2 C45.2 C46.2 C47.2 C48.2 C49.2 C50.2 C51.2 C52.1 C53.1 C54.2 C55.2 C56.2 C58.2 C59.1 C60.2 C62.2 C63.2 C64.2 C65.2 C66.2 C67.2 C68.2 C69.2 C70.2 C71.2 C72.2 C73.2 C74.2 C75.1 C76.2 C77.2 C78.2 C79.2 C80.2 C81.2 C82.2 C83.2 C84.2 C88.2 C90.2 D1.1 D2.1 D3.A(ANODE) D10.2 D11.1 D12.1 D13.1 D14.1 D15.1 D16.1 D20.1 D21.1(ANODE) D22.2(ANODE) D23.1(ANODE) J1.A1(GND1) J1.B1(GND) J2.2 J3.3 J4.3 J6.3 J7.3 J8.3 J8.5 J8.7 J8.9 J9.1 J10.A1(GND_1) J10.A12(GND_2) J10.B1(GND_3) J10.B12(GND_4) J11.1 J13.6 LED1.K(CATHODE) LED2.K(CATHODE) LED4.K(CATHODE) NTC0.1 NTC1.1 Q1.1(G) Q4.2(S) Q10.1(S) Q10.2(S) Q10.3(S) Q11.1(S) Q11.2(S) Q11.3(S) Q14.2(S) R1.1 R6.2 R7.1 R9.1 R15.2 R16.2 R38.2 R50.1 R55.2 R57.1 R60.2 R65.1 R69.2 R70.1 R71.1 R74.2 R76.2 R78.2 R80.2 R82.2 R85.1 SW1.3 SW1.4 SW2.3 SW2.4 SW3.3 SW3.4 TP3.1 TP7.1 TP9.1 TVS1.A U1.5(VSSB) U1.7(VBOOST) U1.8(VBAT) U1.9(VSSD) U1.25(VSSD) U1.43(VSSA) U1.45(VSSD) U1.58(VSSD) U1.62(P2[0]) U1.63(P2[1]) U1.H(EPAD) U2.4(GND) U2.15(GND1) U3.5(PGND) U3.43(VGND) U3.49(EPAD) U4.6(GND) U4.11(Exp) U5.8(GND)
GND_EARTH1: C74.1 J1.MH1 J1.MH2 J1.MH3 J1.MH4 J1.S1 J1.S2 JMP1.1 JMP1.2 R69.1
VBUS_CTRL: Q12.4(G) Q13.4(G) U3.12(VBUS_CTRL)
VBUS_TYPE-C: C50.1 C90.1 D5.A(ANODE) D19.A(ANODE) FB1.2 Q6.5(DRAIN1) Q6.6(DRAIN2) Q6.7(DRAIN3) Q6.8(DRAIN4) Q12.5(D) Q12.6(D) Q12.7(D) Q12.8(D) R40.1
VCC_IN: D4.K(CATHODE) D5.K(CATHODE) D17.K(CATHODE) R14.2 R41.1
AIN1: C79.1 R73.2 R74.1 SW4.3(NC)
AIN2: C80.1 R75.2 R76.1 SW5.3(NC)
AIN3: C81.1 R77.2 R78.1 SW6.3(NC)
AIN4: C82.1 R79.2 R80.1 SW7.3(NC)
B1_VDDD: C17.1 C20.2 C26.1 C28.2 C37.1 C75.2 D8.2(ANODE) D9.2(ANODE) J3.1 J4.1 J7.1 R3.1 R8.1 R12.2 R13.2 R18.1 R19.1 R34.2 R35.2 R36.2 R46.1 R51.1 TP4.1 U3.6(PVDD) U3.22(VDDD) U3.44(VDDD)
B1_VOUT_DC_EN_H: J6.6 R33.2 U3.25(P0.5)
BAT_TH_SNS: C84.1 R84.1 SW8.3(NC)
BB_IN: C48.1 C49.1 C55.1 Q13.5(D) Q13.6(D) Q13.7(D) Q13.8(D) R45.2 SP2.1
BST1: C36.2 D9.1(CATHODE) U3.1(BST1)
BST2: C35.1 D8.1(CATHODE) U3.11(BST2)
C1: C87.2 C88.1 R73.1 R89.1
C2: C86.2 C87.1 R75.1 R88.1
C3: C85.2 C86.1 R77.1 R87.1
C4: C85.1 C89.2 R79.1 R86.1
CC1: C22.1 D14.2 J6.4 J10.A5(CC1) U3.19(CC1)
CC1_KP: J1.A5(CC1) R70.2
CC2: C25.1 D13.2 J6.5 J10.B5(CC2) U3.18(CC2)
CC2_KP: J1.B5(CC2) R71.2
COMP: C38.1 R42.1 U3.13(COMP)
CSNO: C27.2 R49.1 U3.16(CSNO)
CSPO: C27.1 R47.1 U3.17(CSPO)
DM_GPIO1: D12.2 DM_GPIO1.1 J6.12 J10.A7(D-) J10.B7(D-) U3.21(DM_GPIO1)
DP_GPIO0: D11.2 DP_GPIO0.1 J6.11 J10.A6(D+) J10.B6(D+) U3.20(DP_GPIO0)
HG1: HG1.1 Q8.4(G) U3.2(HG1)
HG2: HG2.1 Q7.4(G) U3.10(HG2)
I2C0_SCL: J7.6 R31.2 R35.1 U3.42(P3.1)
I2C0_SDA: J7.7 R30.2 R34.1 U3.41(P3.0)
I2C_SCL: J3.4 J4.4 R4.1 R31.1 U1.38(P12[0])
I2C_SDA: J3.6 J4.6 R30.1 R63.1 U1.39(P12[1])
IIN_CSN: SP1.2 U3.48(CSNI)
IIN_CSP: SP2.2 U3.47(CSPI)
IOUT_CSN: R49.2 SP4.1
IOUT_CSP: R47.2 SP3.1
KP3_UART_RX: J3.8 J4.8 R26.1 U1.21(P12[7])
KP3_UART_TX: J3.10 J4.10 R25.1 U1.20(P12[6])
KP_CLK: J2.4 U1.12(P1[1])
KP_DM: D1.2 J1.A7(D-) J1.B7(D-) R68.1
KP_DP: D2.2 J1.A6(D+) J1.B6(D+) R67.1
KP_IO: J2.5 U1.11(P1[0])
KP_VBUS_IN: D20.2 J1.A4(VBUS_1) J1.B4(VBUS_2) Q1.3(D) R62.1
KP_VBUS_P: D4.A(ANODE) J3.2 J4.2 Q3.3(D) R4.2 R61.1 R62.2 R63.2 R64.2
LG1: LG1.1 Q11.4(G) U3.4(LG1)
LG2: LG2.1 Q10.4(G) U3.7(LG2)
LOAD_SWITCH_EN_H: J7.4 R44.1 U3.28(P2.0)
NTCP0: C52.2 NTC0.2 NTCP0.1 R46.2 U3.23(CSP_GPIO2)
NTCP1: C59.2 NTC1.2 NTCP1.1 R51.2 U3.24(CSN_GPIO3)
P1_3/AIN4: J7.2 SW7.2(COMMON) U3.34(P1.3)
P1_4/AIN3: J7.5 SW6.2(COMMON) U3.33(P1.4)
P1_7/BAT_TH_SNS: J6.8 SW8.2(COMMON) U3.30(P1.7)
P5LP1_2: SW1.1 SW1.2 U1.13(P1[2])
P5LP1_4: R66.1 U1.15(P1[4])
P5LP2_2: U1.64(P2[2])
P5LP2_3: U1.65(P2[3])
P5LP2_4: U1.66(P2[4])
P5LP_SIO_VREF: R7.2 R8.2 U1.48(P0[0])
P5LP_VCCD: C9.1 C67.1 C76.1 C77.1 U1.26(VCCD) U1.57(VCCD)
P5LP_VDD: C2.1 C3.1 C4.1 C6.1 C7.1 C8.1 C10.1 C65.1 C66.1 C68.1 C70.1 C71.1 C72.1 C73.1 J2.1 R2.1 R64.1 U1.17(VDDIO1) U1.24(VDDD) U1.35(VDDIO3) U1.44(VDDA) U1.52(VDDIO) U1.59(VDDD) U1.67(VDDIO2)
RESET: C13.2 J3.5 J4.5 J8.10 R19.2 SW3.1 SW3.2 U1.3(P12[4]) U3.40(XRES)
SOURCE_BUCK_EN_H: C21.1 J7.12 R22.1 U3.39(P2.3)
SOURCE_FAULT_FLAG: J7.11 R54.1 U3.38(P2.2)
SOURCE_OUTPUT_V_SELECT: J7.8 Q14.1(G) R55.1 U3.29(P2.1)
SW_1: C36.1 L2.1 Q8.1(S) Q8.2(S) Q8.3(S) Q11.5(D) SW_1.1 U3.3(SW1)
SW_2: C35.2 L2.2 Q7.1(S) Q7.2(S) Q7.3(S) Q10.5(D) SW_2.1 U3.9(SW2)
SWD_CLK: J7.9 J8.4 R10.2 R12.1 U3.36(P1.1)
SWD_DAT: J7.10 J8.2 R11.2 R13.1 U3.37(P1.0)
SWDCLK: J3.7 J4.7 R10.1 U1.47(P12[3])
SWDIO: J3.9 J4.9 R11.1 U1.46(P12[2])
TH: J13.1 R83.1
UART2_RX: R25.2 SW4.1(NO)
UART2_RX/AIN1: J6.9 SW4.2(COMMON) U3.31(P1.6)
UART2_TX: R26.2 SW5.1(NO)
UART2_TX/AIN2: J6.10 SW5.2(COMMON) U3.32(P1.5)
UART_CTS: R9.2 U1.61(P15[5])
USB_V_SENSE: R1.2 R2.2 U1.19(P1[7])
USER_STATUS_LED: J6.7 R21.1 U3.27(P0.7)
USER_SWITCH: J6.2 R17.1 U3.26(P0.6)
VOUT: C42.1 C45.1 C46.1 C47.1 C51.1 C78.1 D22.1(CATHODE) D23.2(CATHODE) Q5.5(D) Q5.6(D) Q5.7(D) Q5.8(D) Q7.5(D) R39.1 R72.2 U3.8(VOUT) VOUT.1
VOUT_BUCK: C16.1 C18.2 C32.1 C33.1 C60.1 L1.2 R29.1 U4.1(VIN1) U4.2(VIN2)
VOUT_DC: C57.1 D15.2 J9.2 R48.2 R90.2 SP4.2 TP10.1
VOUT_DC_MEAS: C83.1 R81.2 R82.1 U3.35(P1.2)
VOUT_U2: C40.1 Q6.1(SOURCE3) Q6.2(SOURCE2) Q6.3(SOURCE1) R53.2 U4.3(VOUT1) U4.4(VOUT2)
VS_IN: C19.1 C63.1 C64.1 D17.A(ANODE) D18.A(ANODE) J11.2 R58.2 U5.1(VIN)
VTARG: C11.2 D6.A(ANODE) J8.1 TVS1.K
VTARG_MEAS: R3.2 R65.2 U1.32(P3[3])
XRES: J2.3 U1.10(~{XRES})
N01675: C61.1 L1.1 U5.7(NC) U5.9(SW)
N01977: C61.2 U5.6(BST)
N02113: C41.1 U4.7(dV/dt)
N02139: R16.1 R22.2 R58.1 U5.2(EN)
N02147: C18.1 R15.1 R29.2 R59.1 R60.1 U5.3(FB)
N02197: R54.2 U5.5(PG)
N02205: R56.2 R57.2 U5.4(COMP)
N02555: Q14.3(D) R59.2
N15498: C12.2 R17.2 R20.2 SW2.1 SW2.2
N16041498: C54.1 C56.1 D16.2 FB1.1 J10.A4(VBUS_1) J10.A9(VBUS_2) J10.B4(VBUS_3) J10.B9(VBUS_4) TP8.1
N16043536: C53.2 D10.1 J10.SH1 J10.SH2 J10.SH3 J10.SH4 R50.2
N16124091: R53.1 U4.9(ILIM)
N16800802: LED3.A(ANODE) R18.2
N16801019: LED3.K(CATHODE) R21.2
N16919447: C31.2 R41.2 TP6.1 U3.46(VIN)
N17059836: C34.1 R40.2 U3.14(VBUS_C)
N17062103: C29.2 U3.45(VCCD)
N17063422: C30.1 R39.2 U3.15(VOUT_EA)
N17316342: C39.1 R42.2
N17354900: D18.K(CATHODE) D19.K(CATHODE) R32.2 TP5.1
N17354936: C23.2 C24.2 R32.1 U2.13(I)
N17354948: C14.1 C15.1 R27.2 U2.9(Q)
N17368419: Q1.2(S) Q2.2(S) Q3.2(S) R5.2
N17368440: Q2.3(D) Q3.1(G) R6.1
N17368442: D3.K(CATHODE) Q2.1(G) R5.1
N17400441: C62.1 R56.1
N17416139: Q9.5(D) Q9.6(D) Q9.7(D) Q9.8(D) R48.1 SP3.2
N17416161: D7.1(CATHODE) Q5.1(S) Q5.2(S) Q5.3(S) Q9.1(S) Q9.2(S) Q9.3(S) R43.1
N17416246: C43.1 C44.1 Q8.5(D) R45.1 SP1.1
N17416442: D7.2(ANODE) Q4.3(D) Q5.4(G) Q9.4(G) R43.2
N17416547: C57.2 C58.1
N17416846: Q4.1(G) R33.1 R36.1 R38.1
N17422796: Q12.1(S) Q12.2(S) Q12.3(S) Q13.1(S) Q13.2(S) Q13.3(S)
N17479997: D6.K(CATHODE) R14.1
N17481687: LED4.A(ANODE) R28.2
N17511481: R52.2 U4.10(VG)
N17618145: D21.2(CATHODE) R72.1
N17631535: R83.2 R84.2 R85.2 TP11.1
N17633702: C89.1 R81.1 R90.1
N17633741: J13.2 R86.2
N17633795: J13.3 R87.2
N17633797: J13.4 R88.2
N17633812: J13.5 R89.2
N17661501: R44.2 U4.8(EN/Fault)
N17663299: Q6.4(GATE) R52.1
N19965120: C1.1 U1.31(P3[2])
N19965125: C69.1 U1.53(P0[4])
N19965127: C5.1 U1.42(VCCA)
N19965162: R67.2 U1.22(P15[6]_D+)
N19965164: R68.2 U1.23(P15[7]_D-)
N19965683: LED2.A(ANODE) R61.2
N19965698: LED1.A(ANODE) R66.2

Not connected (* = marked no-connect by the designer): J1 A8(SBU1)* B8(SBU2)*; J8 6* 8*; J10 A2(TX1+)* A3(TX1-)* A8(SBU1)* A10(RX2-)* A11(RX2+)* B2(TX2+)* B3(TX2-)* B8(SBU2)* B10(RX1-)* B11(RX1+)*; SW6 1(NO)*; SW7 1(NO)*; SW8 1(NO)*; U1 1(P2[6])* 2(P2[7])* 4(P12[5])* 6(IND)* 14(P1[3])* 16(P1[5])* 18(P1[6])* 27(P15[0])* 28(P15[1])* 29(P3[0])* 30(P3[1])* 33(P3[4])* 34(P3[5])* 36(P3[6])* 37(P3[7])* 40(P15[2])* 41(P15[3])* 49(P0[1])* 50(P0[2])* 51(P0[3])* 54(P0[5])* 55(P0[6])* 56(P0[7])* 60(P15[4])* 68(P2[5])*; U2 1(NC0)* 2(NC1)* 3(NC2)* 5(NC3)* 6(NC4)* 7(NC5)* 8(NC6)* 10(NC7)* 11(NC8)* 12(NC9)* 14(NC10)*; U4 5(NC)*

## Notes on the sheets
sheet 1
- REVISION HISTORY
- Orig. of
  Change
- REV
- DESCRIPTION OF CHANGE
- DESCRIPTION OF CHANGE
- DATE
- 01
- Initial Release
- 2022/04/05
- 02
- Q5 MOSFET short between Drain to Source removed.
- 2022/07/25
- Legal Disclaimer:
- The information given in this document shall in no event be regarded
  as a guarantee of conditions or characteristics. With respect to any
  examples or hints given herein, any typical values stated herein
  and/or any information regarding the application of the device,
  Infineon Technologies hereby disclaims any and all warranties and
  liabilities of any kind, including without limitation, warranties of
  non-infringement of intellectual property rights of any third party.
sheet 2
- Accessories
- PCBA label
- Bumper
- Number of bumpers can be based on the PCB size
- Legal Disclaimer:
- The information given in this document shall in no event be regarded
  as a guarantee of conditions or characteristics. With respect to any
  examples or hints given herein, any typical values stated herein
  and/or any information regarding the application of the device,
  Infineon Technologies hereby disclaims any and all warranties and
  liabilities of any kind, including without limitation, warranties of
  non-infringement of intellectual property rights of any third party.
sheet 3
- KITPROG3 TYPE-C CONNECTOR
- KIT PROG OVER VOLTAGE
  PROTECTION CIRCUIT
- PSoC 5LP POWER
- DECOUPLING CAPACITORS
- I2C PULL-UPS
- MODE SWITCH
- KITPROG3 STATUS LED
- KITPROG3 HW REVISION
- PSoC 5LP BASED KITPROG3
- "NOTE: GND IS
  READ AS BINARY
   "1" AND
  FLOATING AS "0"
- Bit 0
- Bit 1
- TARGET VOLTAGE MONITORING
- Bit 2
- Bit 3
- Bit 4
- ID = 0x03
- KP POWER LED
- SAR Bypass
  Capacitor
- KITPROG3 TARGET INTERFACE
   HEADER
- Legal Disclaimer:
- The information given in this document shall in no event be regarded
  as a guarantee of conditions or characteristics. With respect to any
  examples or hints given herein, any typical values stated herein
  and/or any information regarding the application of the device,
  Infineon Technologies hereby disclaims any and all warranties and
  liabilities of any kind, including without limitation, warranties of
  non-infringement of intellectual property rights of any third party.
- DEL-SIG BYPASS
  CAPACITOR
sheet 4
- Legal Disclaimer:
- The information given in this document shall in no event be regarded
  as a guarantee of conditions or characteristics. With respect to any
  examples or hints given herein, any typical values stated herein
  and/or any information regarding the application of the device,
  Infineon Technologies hereby disclaims any and all warranties and
  liabilities of any kind, including without limitation, warranties of
  non-infringement of intellectual property rights of any third party.
sheet 5
- NTC0 NEAR
  TYPE-C CONNECTOR (J10)
- NTC1 NEAR
  BUCK BOOST
  L2, Q7, Q8, Q10, Q11
- Legal Disclaimer:
- The information given in this document shall in no event be regarded
  as a guarantee of conditions or characteristics. With respect to any
  examples or hints given herein, any typical values stated herein
  and/or any information regarding the application of the device,
  Infineon Technologies hereby disclaims any and all warranties and
  liabilities of any kind, including without limitation, warranties of
  non-infringement of intellectual property rights of any third party.
sheet 6
- INPUT SUPPLY FROM KITPROG3 &
  10 PIN SWD HEADER
- 5V LDO
- POWER LED
- SWD SIGNALS
- I2C SIGNALS
- STATUS LED/ USER LED
- USER SWITCH
- RESET CIRCUIT
- UART SIGNAL
- Legal Disclaimer:
- The information given in this document shall in no event be regarded
  as a guarantee of conditions or characteristics. With respect to any
  examples or hints given herein, any typical values stated herein
  and/or any information regarding the application of the device,
  Infineon Technologies hereby disclaims any and all warranties and
  liabilities of any kind, including without limitation, warranties of
  non-infringement of intellectual property rights of any third party.
sheet 7
- INPUT
  9V to 22V
- BLUE COLOR
- 2PIN INPUT
  DC TERMINAL
- NOTE:FOR R57 WE ARE REPLACING WITH CAPICATOR .NO CHANGES IN LAYOUT .
- Legal Disclaimer:
- The information given in this document shall in no event be regarded
  as a guarantee of conditions or characteristics. With respect to any
  examples or hints given herein, any typical values stated herein
  and/or any information regarding the application of the device,
  Infineon Technologies hereby disclaims any and all warranties and
  liabilities of any kind, including without limitation, warranties of
  non-infringement of intellectual property rights of any third party.
sheet 8
- 10-PIN SWD/JTAG HEADER
- KITPROG3 HEADER
- I/O HEADER
- I/O HEADER
- Legal Disclaimer:
- The information given in this document shall in no event be regarded
  as a guarantee of conditions or characteristics. With respect to any
  examples or hints given herein, any typical values stated herein
  and/or any information regarding the application of the device,
  Infineon Technologies hereby disclaims any and all warranties and
  liabilities of any kind, including without limitation, warranties of
  non-infringement of intellectual property rights of any third party.
sheet 9
- C84, R84 PLACE NEAR PMG1-B1
- VBAT - 20V
  C4 - 16V
  C3 - 12V
  C2 - 8V
  C1 - 4V
- Battery Connector 5-Cell
- C79, C80, C81, C82, C83 PLACE NEAR PMG1-B1
- Legal Disclaimer:
- The information given in this document shall in no event be regarded
  as a guarantee of conditions or characteristics. With respect to any
  examples or hints given herein, any typical values stated herein
  and/or any information regarding the application of the device,
  Infineon Technologies hereby disclaims any and all warranties and
  liabilities of any kind, including without limitation, warranties of
  non-infringement of intellectual property rights of any third party.
sheet 10
- EVAL_PMG1B1_DRP_KIT
- CONTENTS
- PAGE
- DESCRIPTION
- 01
- TITLE & TABLE OF CONTENTS
- 02
- Block Diagram
- 03
- KITPROG3
- 04
- INPUT & BUCK/BOOST CIRCUITS
- 05
- PMG1-B1 CONTROLLER
- 06
- INTERFACE SIGNALS
- 07
- CONNECTOR INTERFACES
- 08
- SOURCE BUCK (27W MAX)
- 09
- BATTERY CELL & TEMPERATURE MONITORING
- 10
- ACCESSORIES
- 11
- REVISION HISTORY
- Drawing Numbers
- PCBA
- 121-60657-01
- PCB
- 600-60657-01
- FAB DRA
- 610-60657-01
- ASSY DRA
- 620-60657-01
- Legal Disclaimer:
- SCH DRA
- 630-60657-01
- The information given in this document shall in no event be regarded
  as a guarantee of conditions or characteristics. With respect to any
  examples or hints given herein, any typical values stated herein
  and/or any information regarding the application of the device,
  Infineon Technologies hereby disclaims any and all warranties and
  liabilities of any kind, including without limitation, warranties of
  non-infringement of intellectual property rights of any third party.
sheet 11
- TYPE-C CONNECTOR
- 2PIN OUTPUT
  LOAD TERMINAL
- KRL2012
- GREEN COLOR
- 5V to 22V
- PLACE C35 AND C36 CLOSE TO THE U3 (PMG1-B1)
- Legal Disclaimer:
- The information given in this document shall in no event be regarded
  as a guarantee of conditions or characteristics. With respect to any
  examples or hints given herein, any typical values stated herein
  and/or any information regarding the application of the device,
  Infineon Technologies hereby disclaims any and all warranties and
  liabilities of any kind, including without limitation, warranties of
  non-infringement of intellectual property rights of any third party.
